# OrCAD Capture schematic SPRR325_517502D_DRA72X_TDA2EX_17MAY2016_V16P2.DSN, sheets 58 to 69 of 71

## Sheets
58 SH69 - POWER MONITOR 2: size B; rev: C
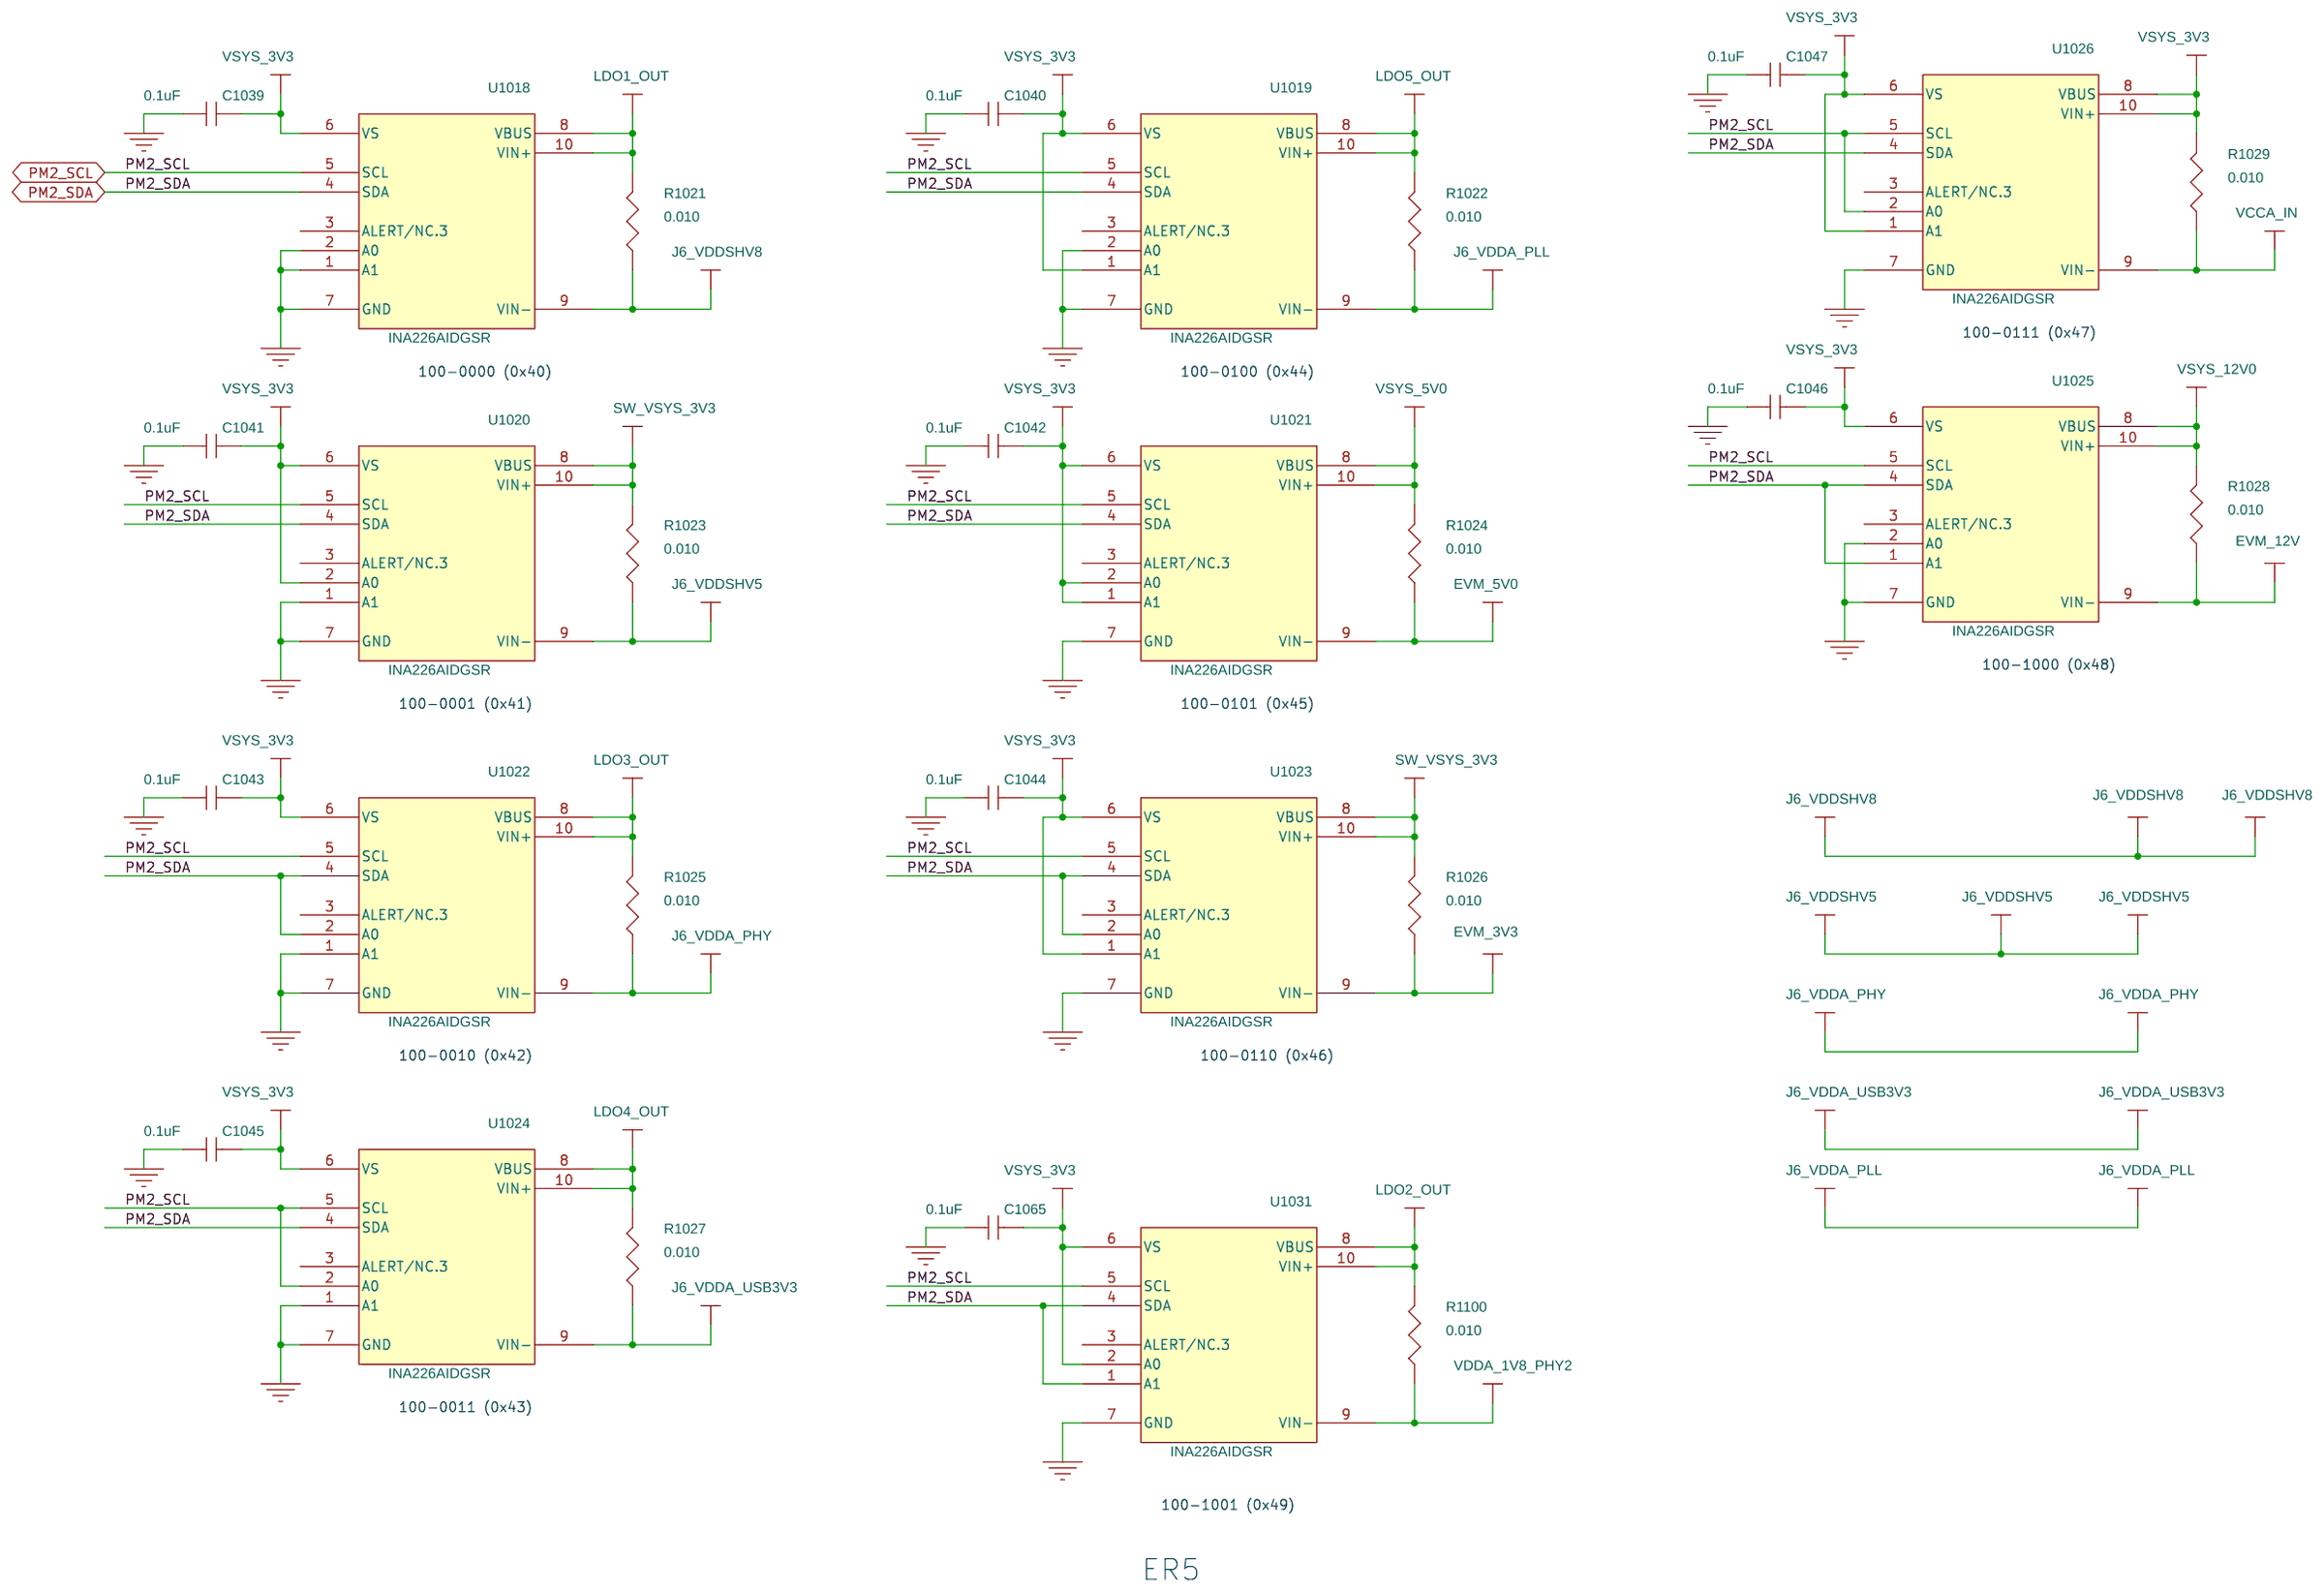
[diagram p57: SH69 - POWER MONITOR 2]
59 SH70 - DARA INTERFACE: size B; rev: C
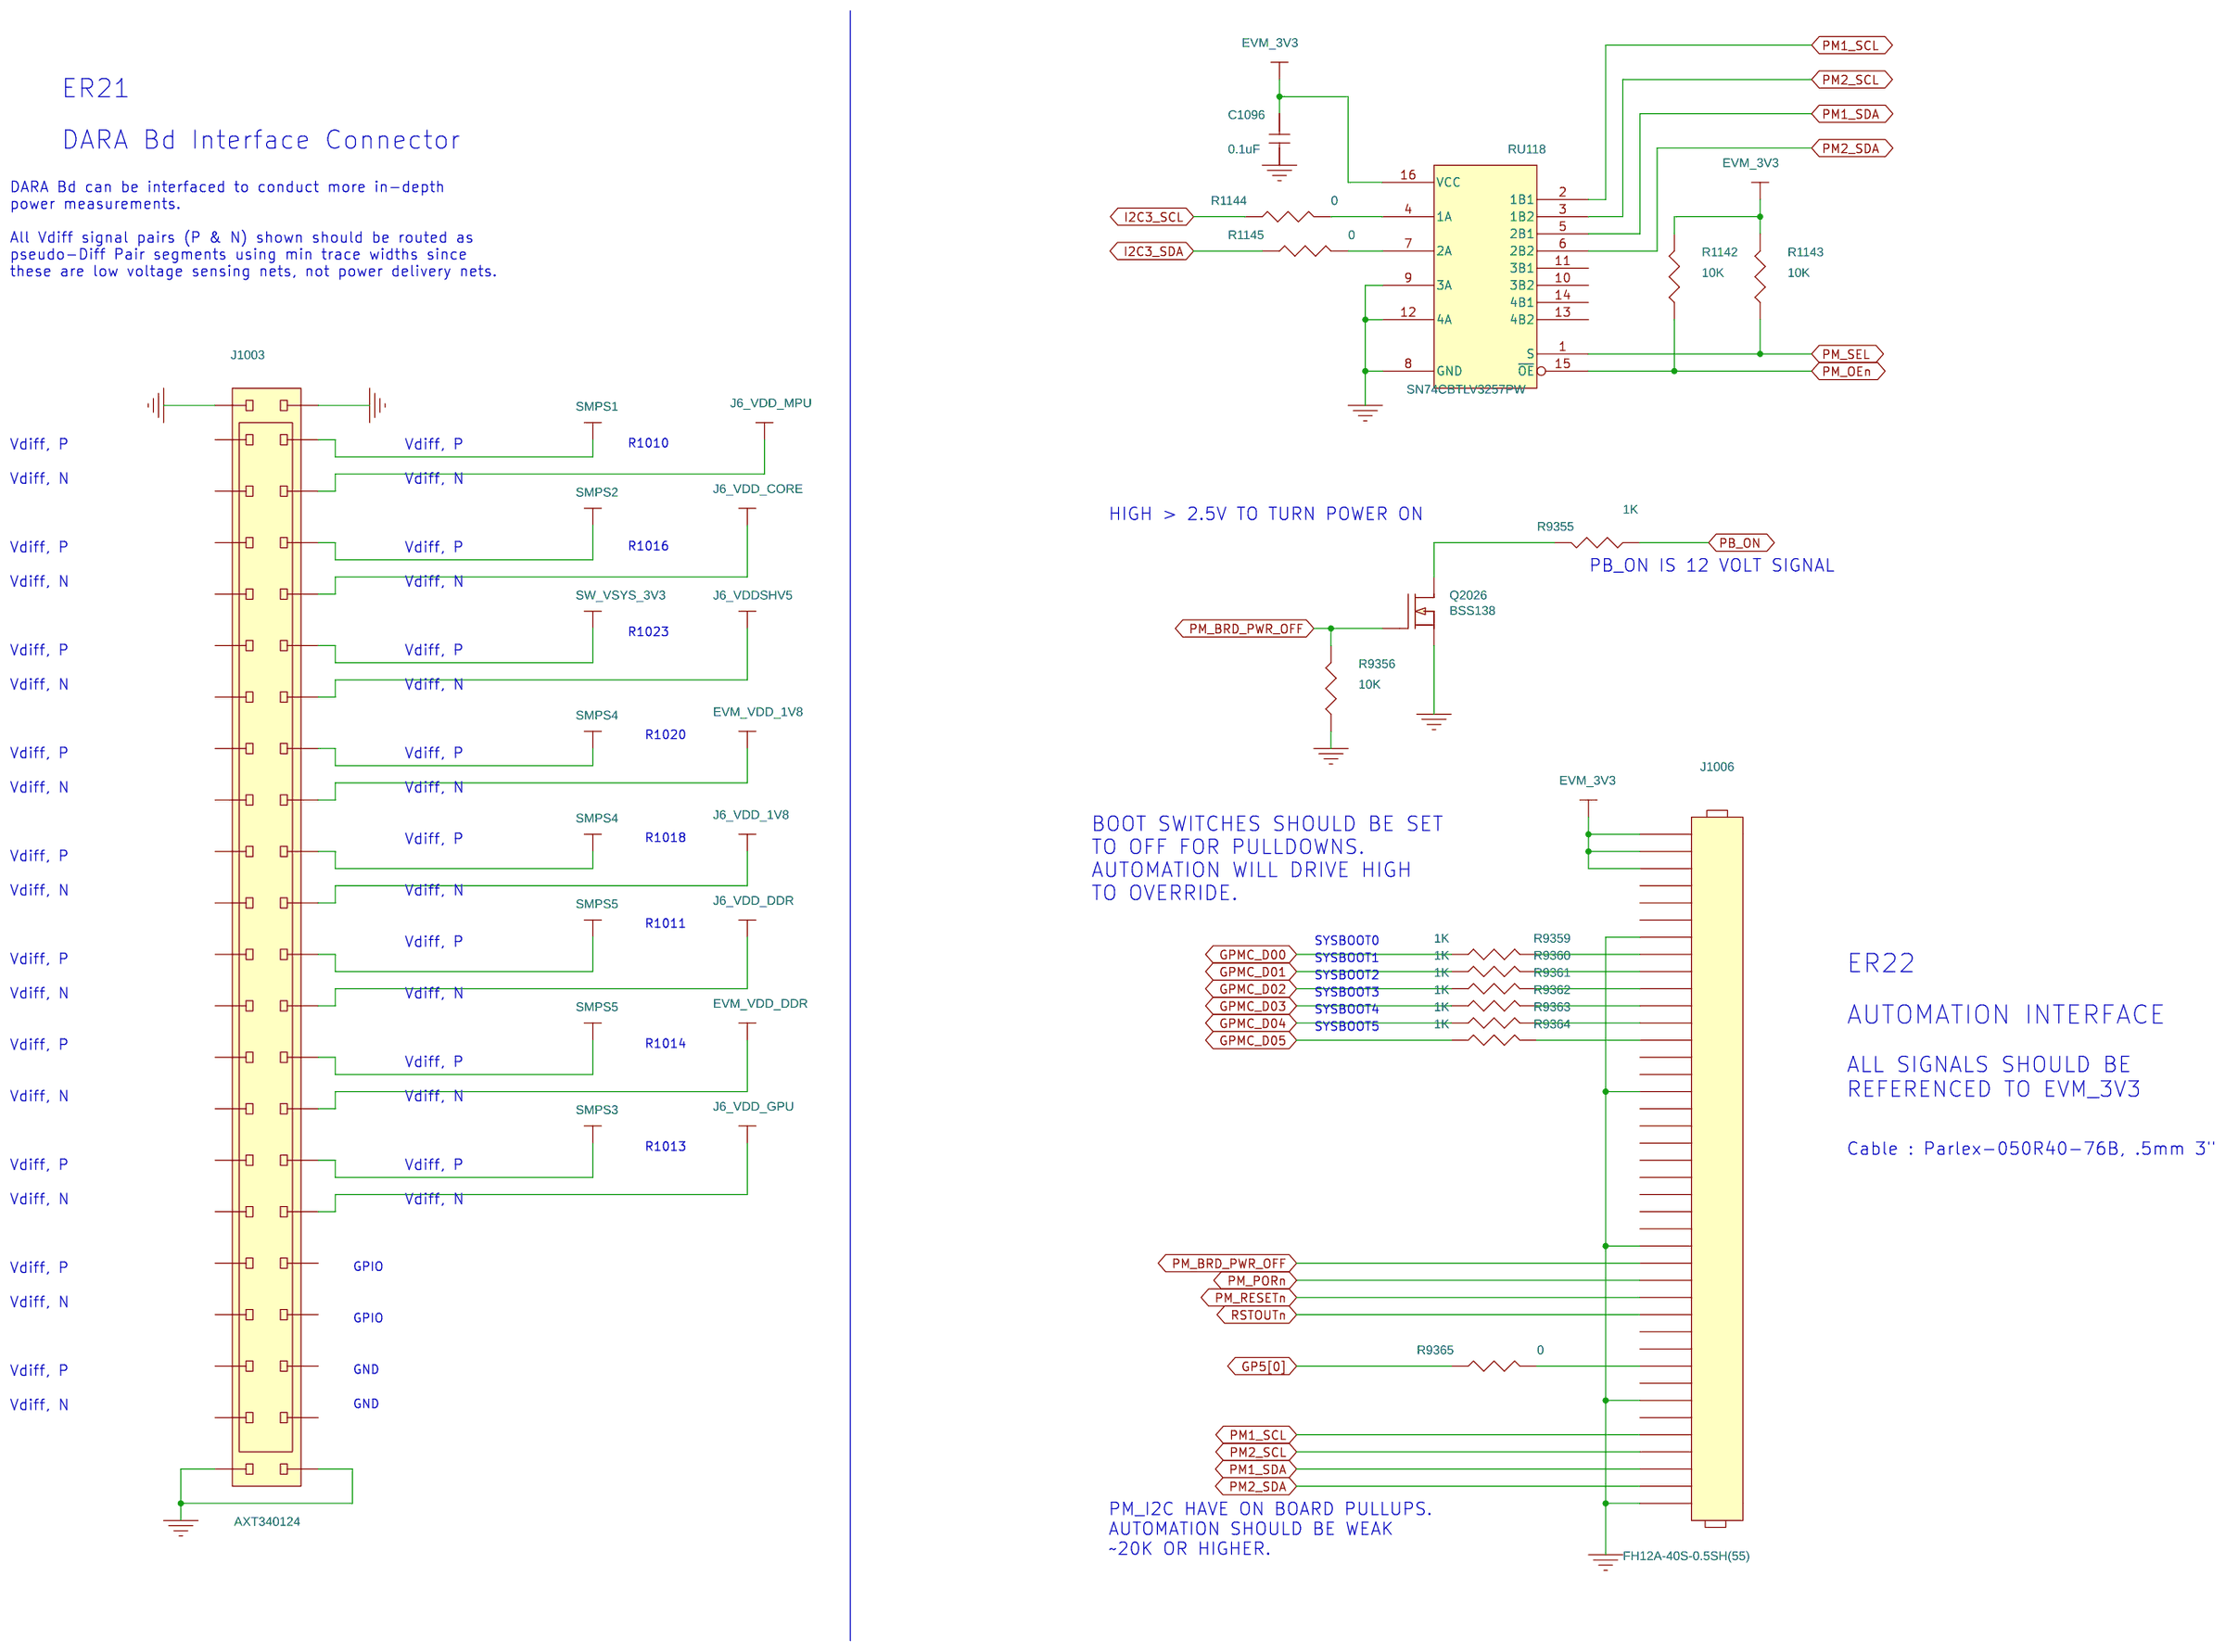
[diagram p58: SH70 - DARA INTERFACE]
60 SH71 - ECN REV B1 TO C
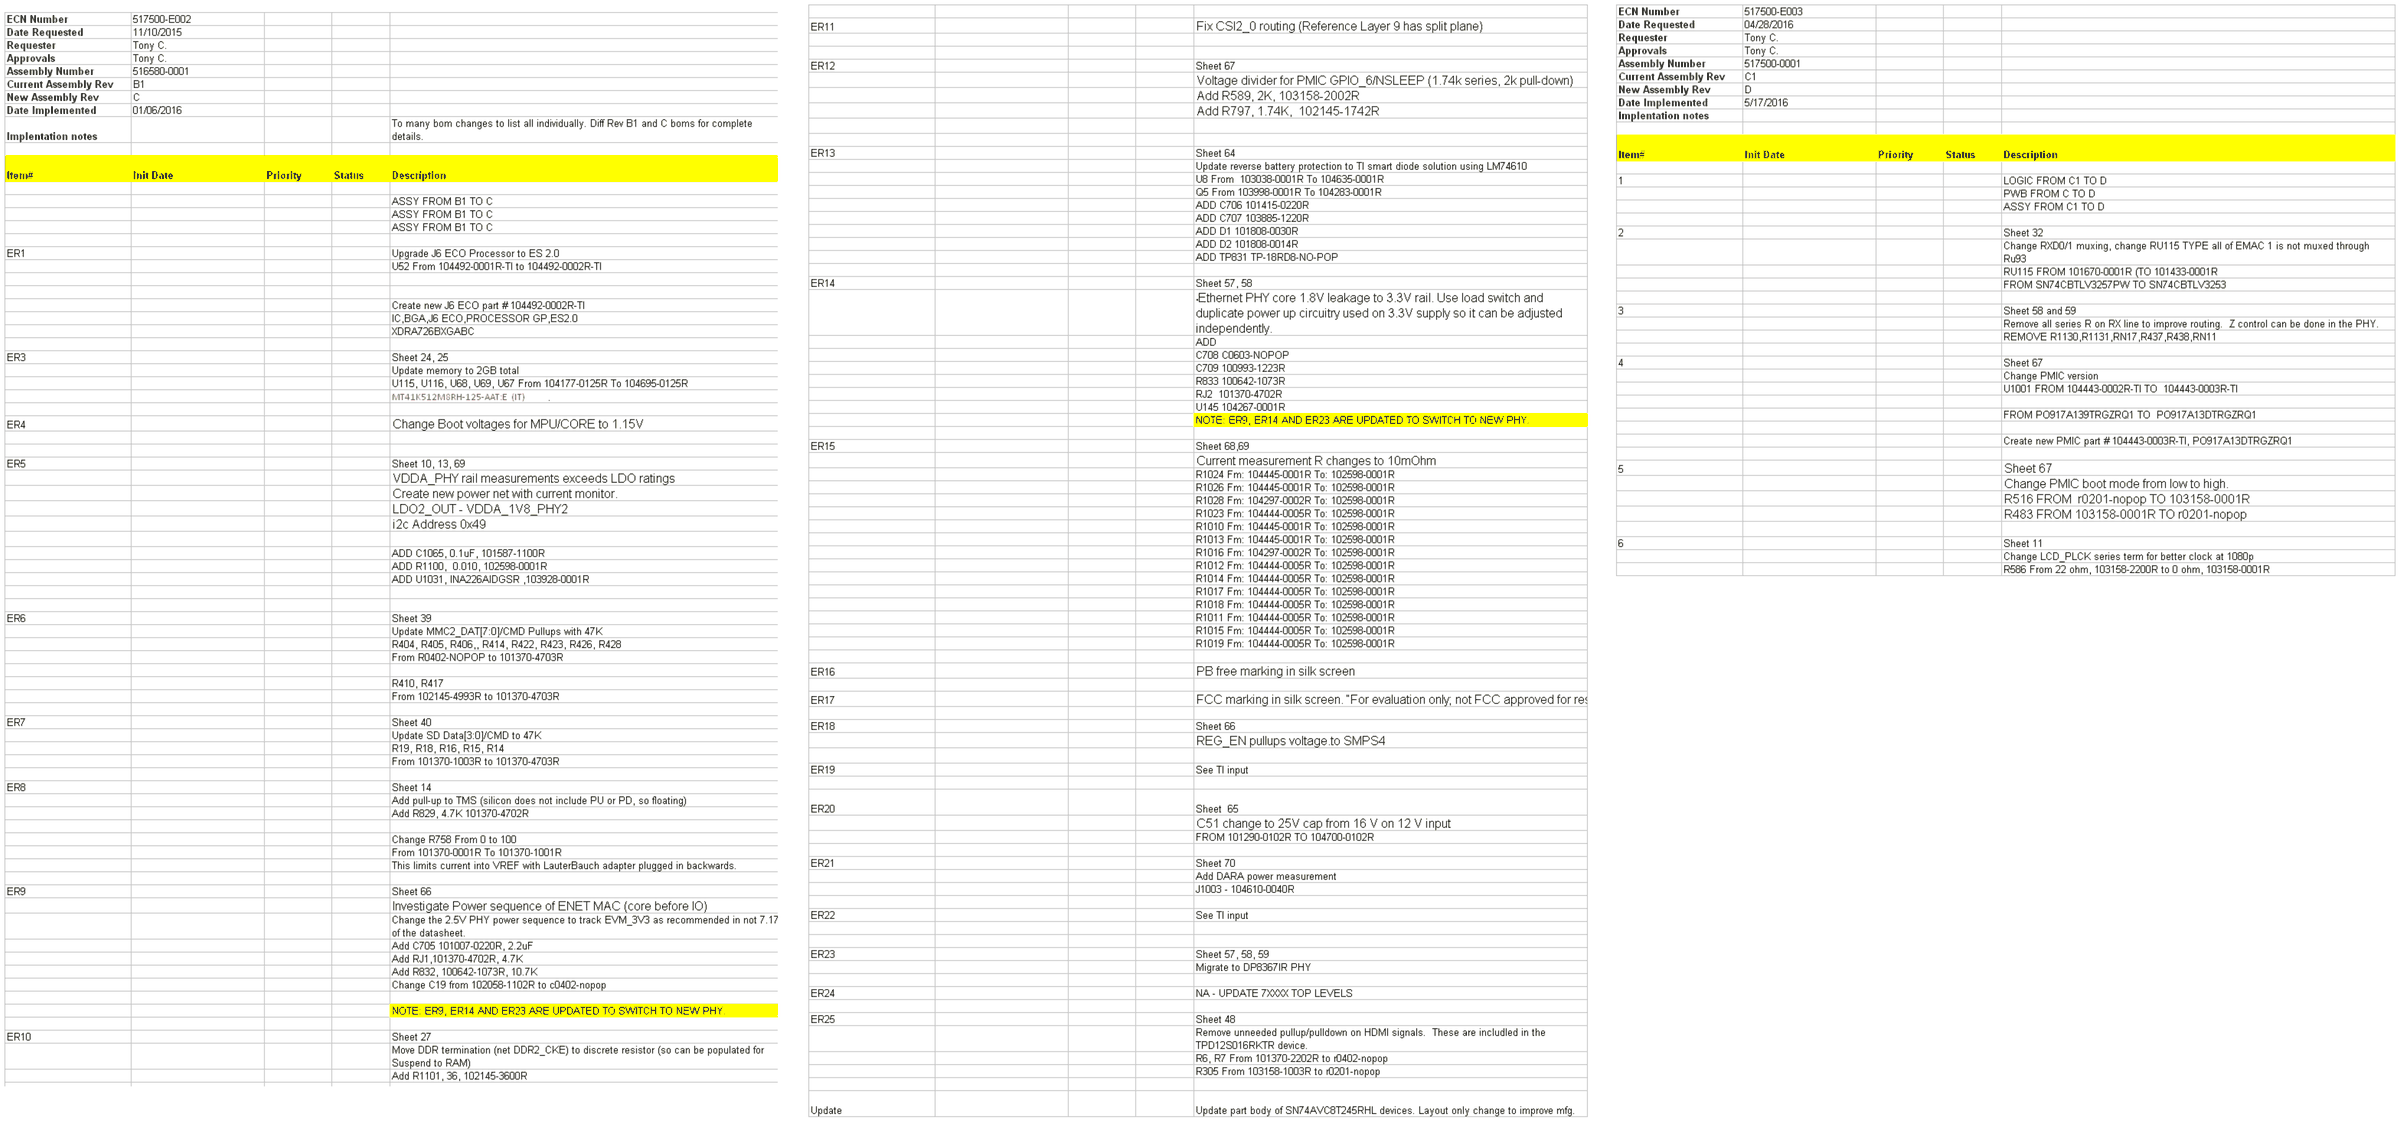
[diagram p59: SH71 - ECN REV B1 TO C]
61 SH04 - SoC SD/MMC IF: size B; rev: A
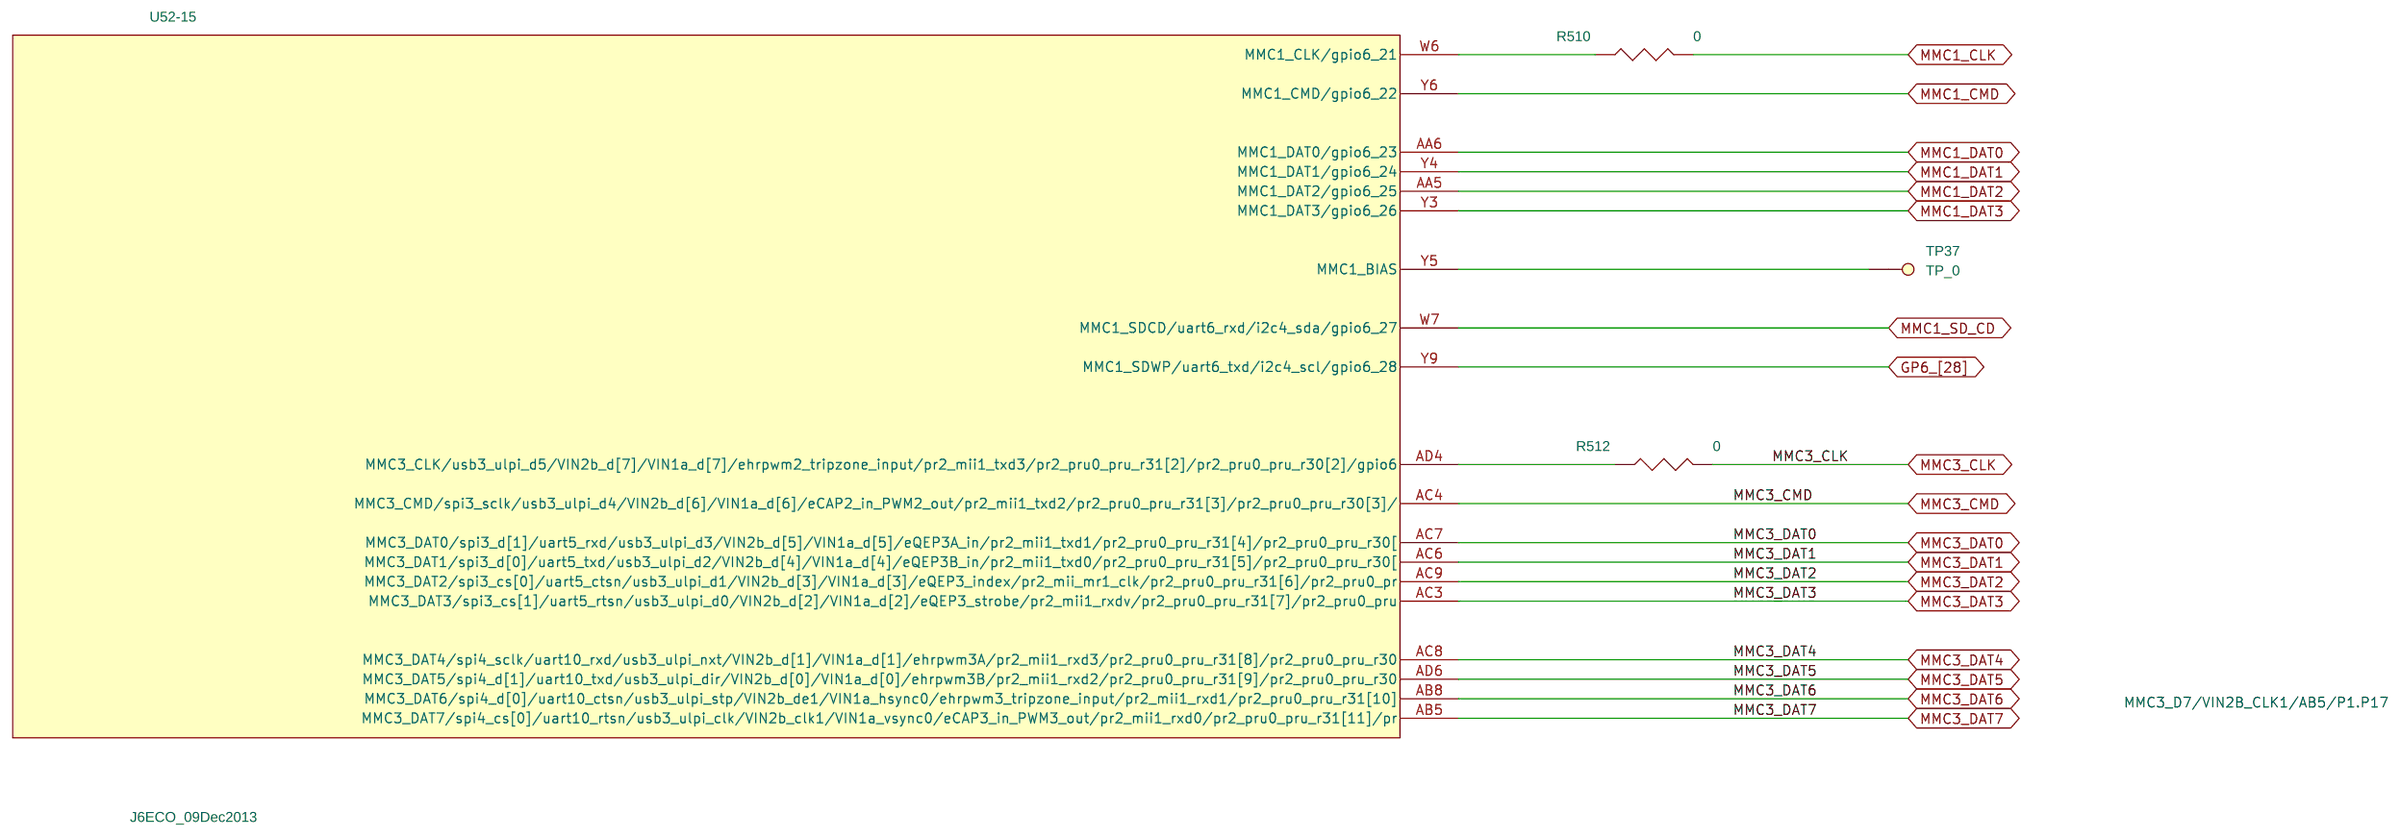
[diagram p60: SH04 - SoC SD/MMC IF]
62 SH03 - SoC SERIAL I/O: size B; rev: C
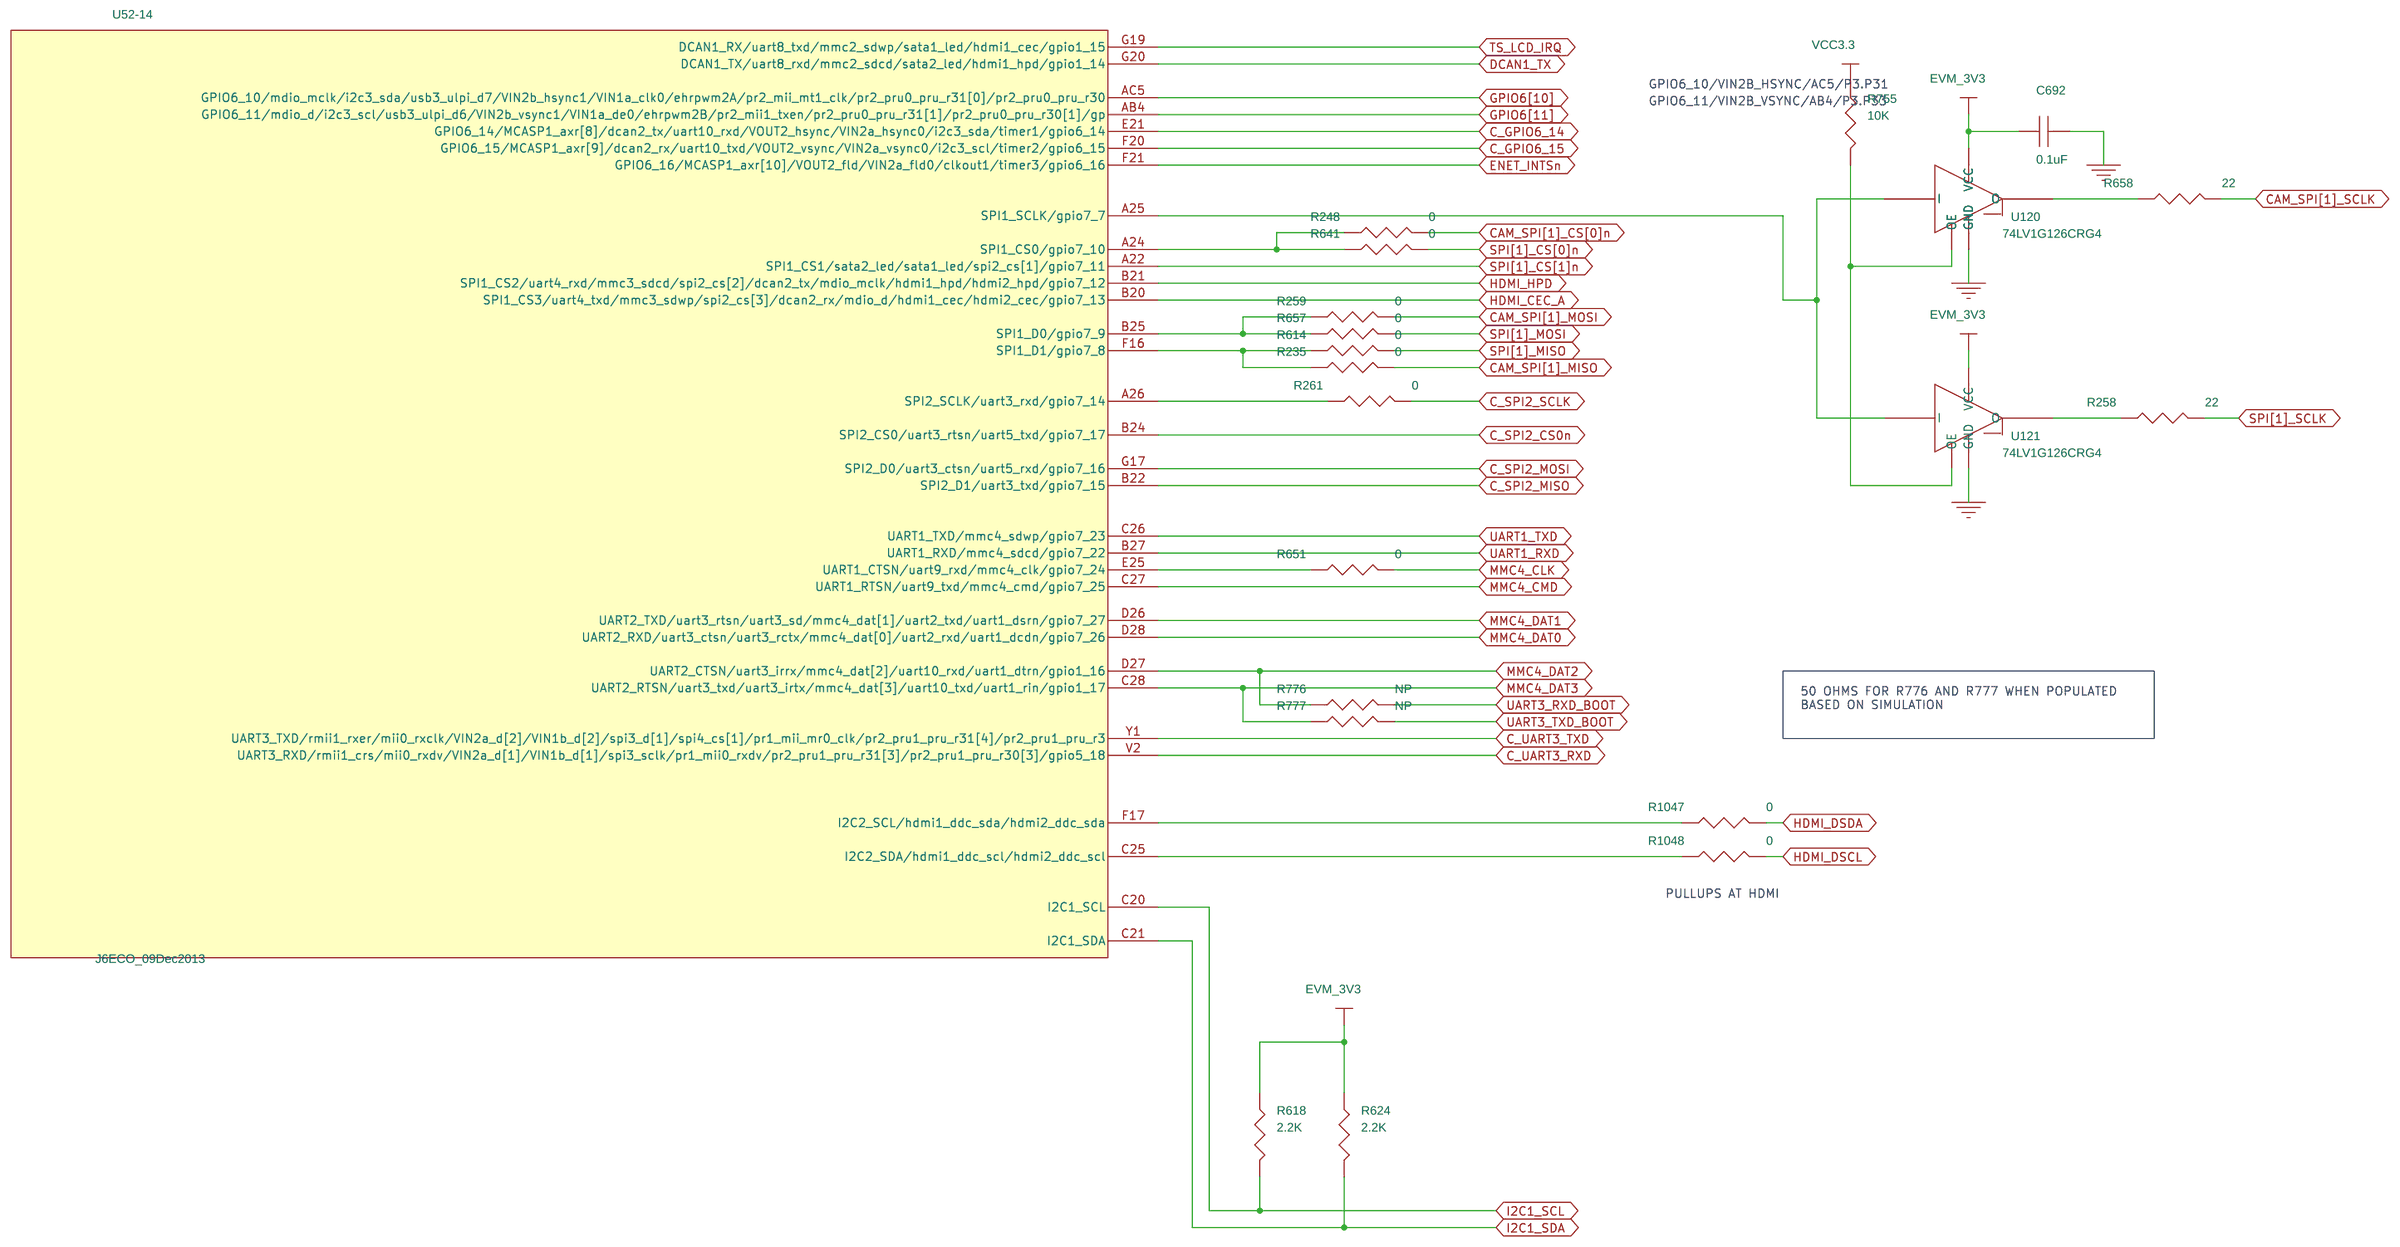
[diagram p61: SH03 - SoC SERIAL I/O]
63 SH29 - MUX B VOUT3/GPMC: size B; rev: C
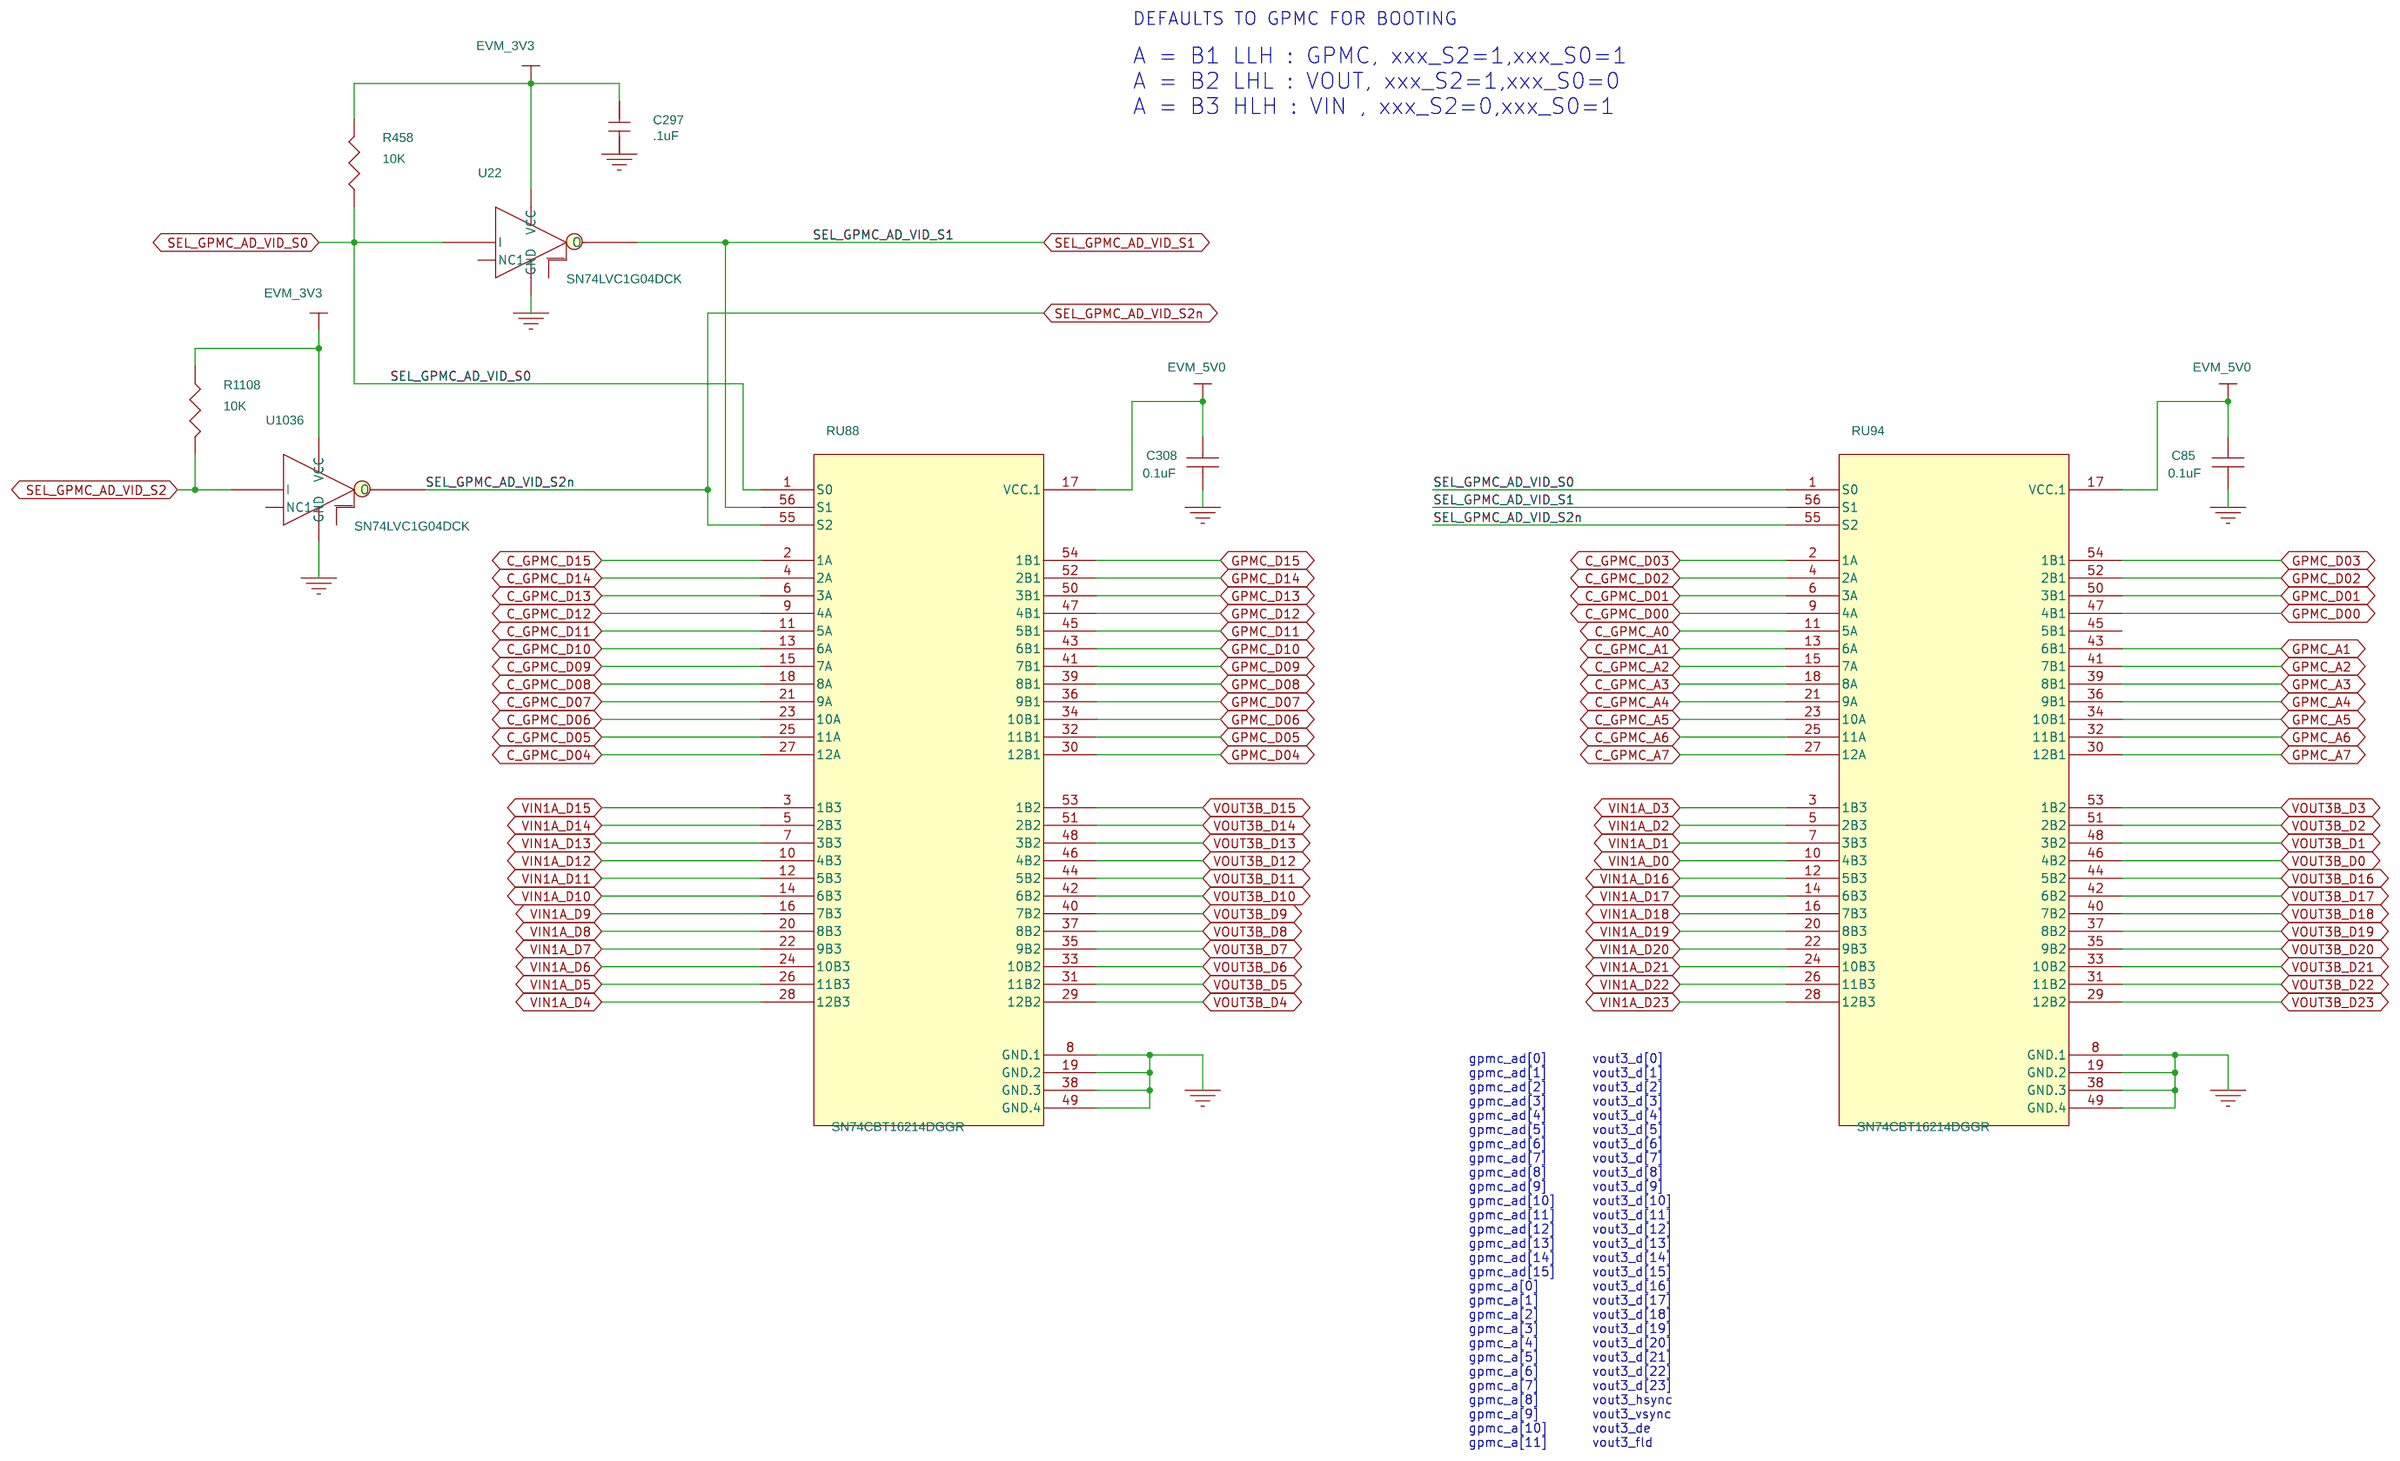
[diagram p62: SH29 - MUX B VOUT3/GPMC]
64 SH06 - SoC ETHERNET/USB: size B; rev: A
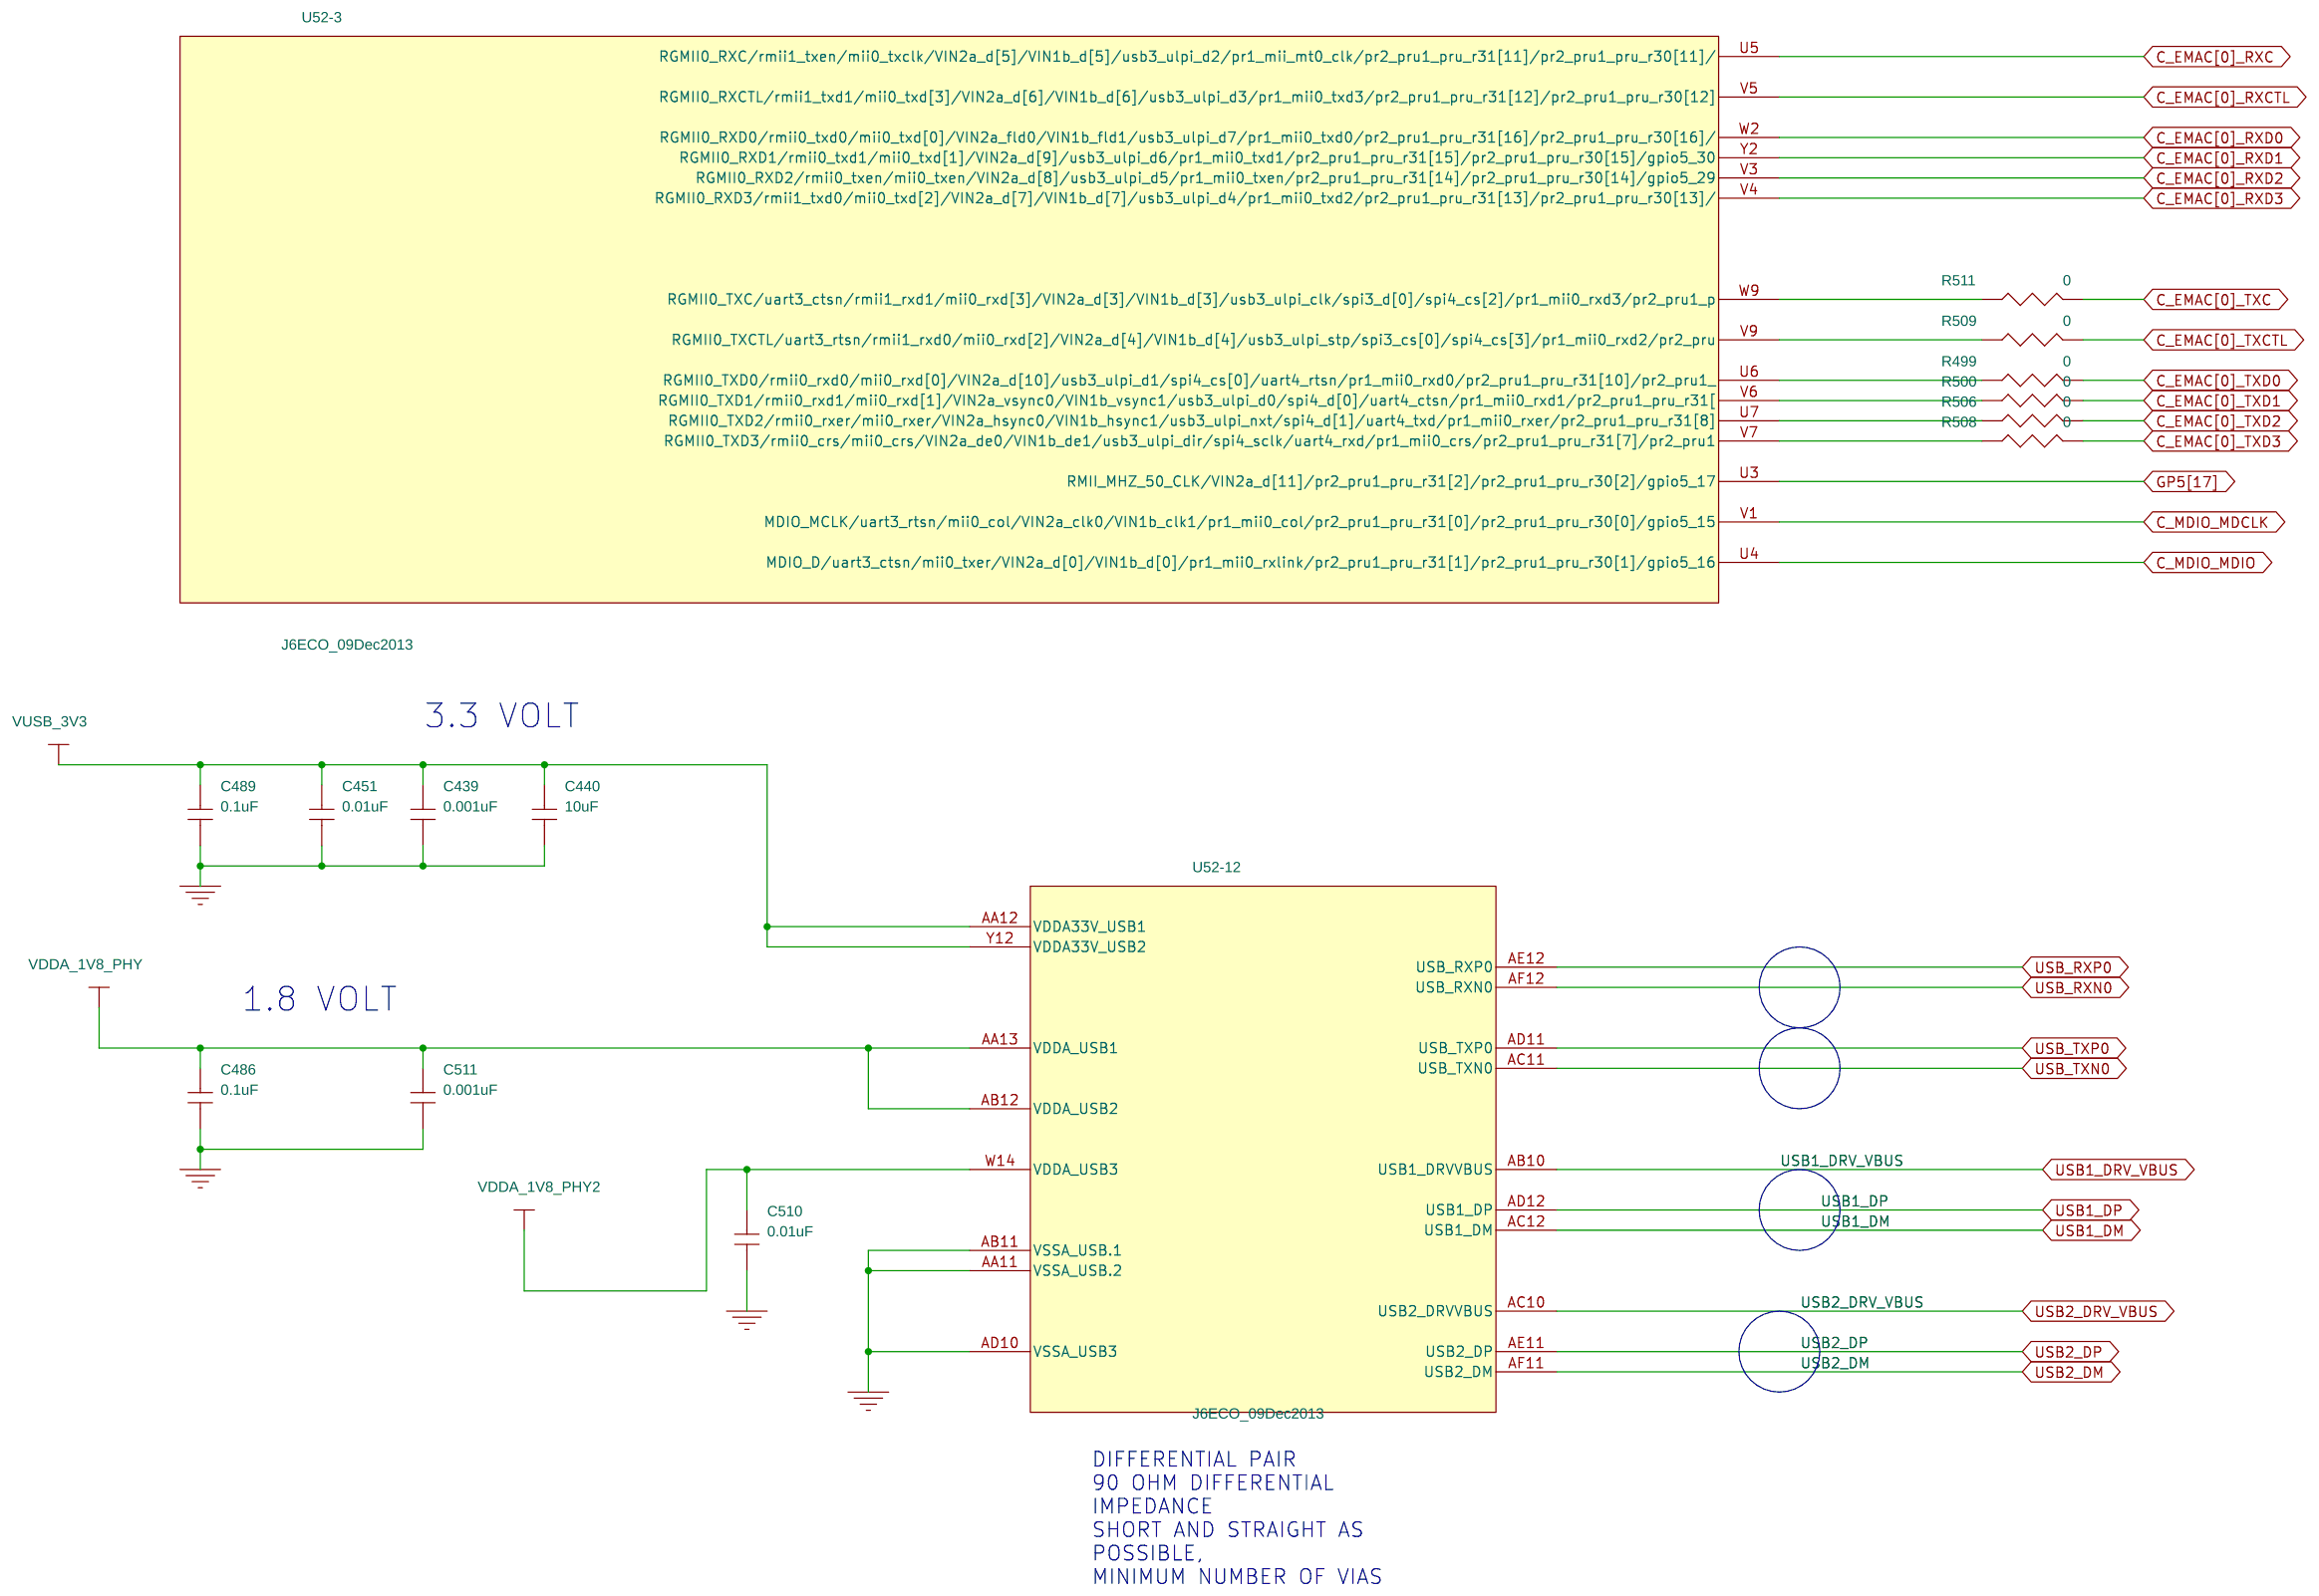
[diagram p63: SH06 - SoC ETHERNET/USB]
65 SH33 - MUX G ENET0/VIN4: size B; rev: C
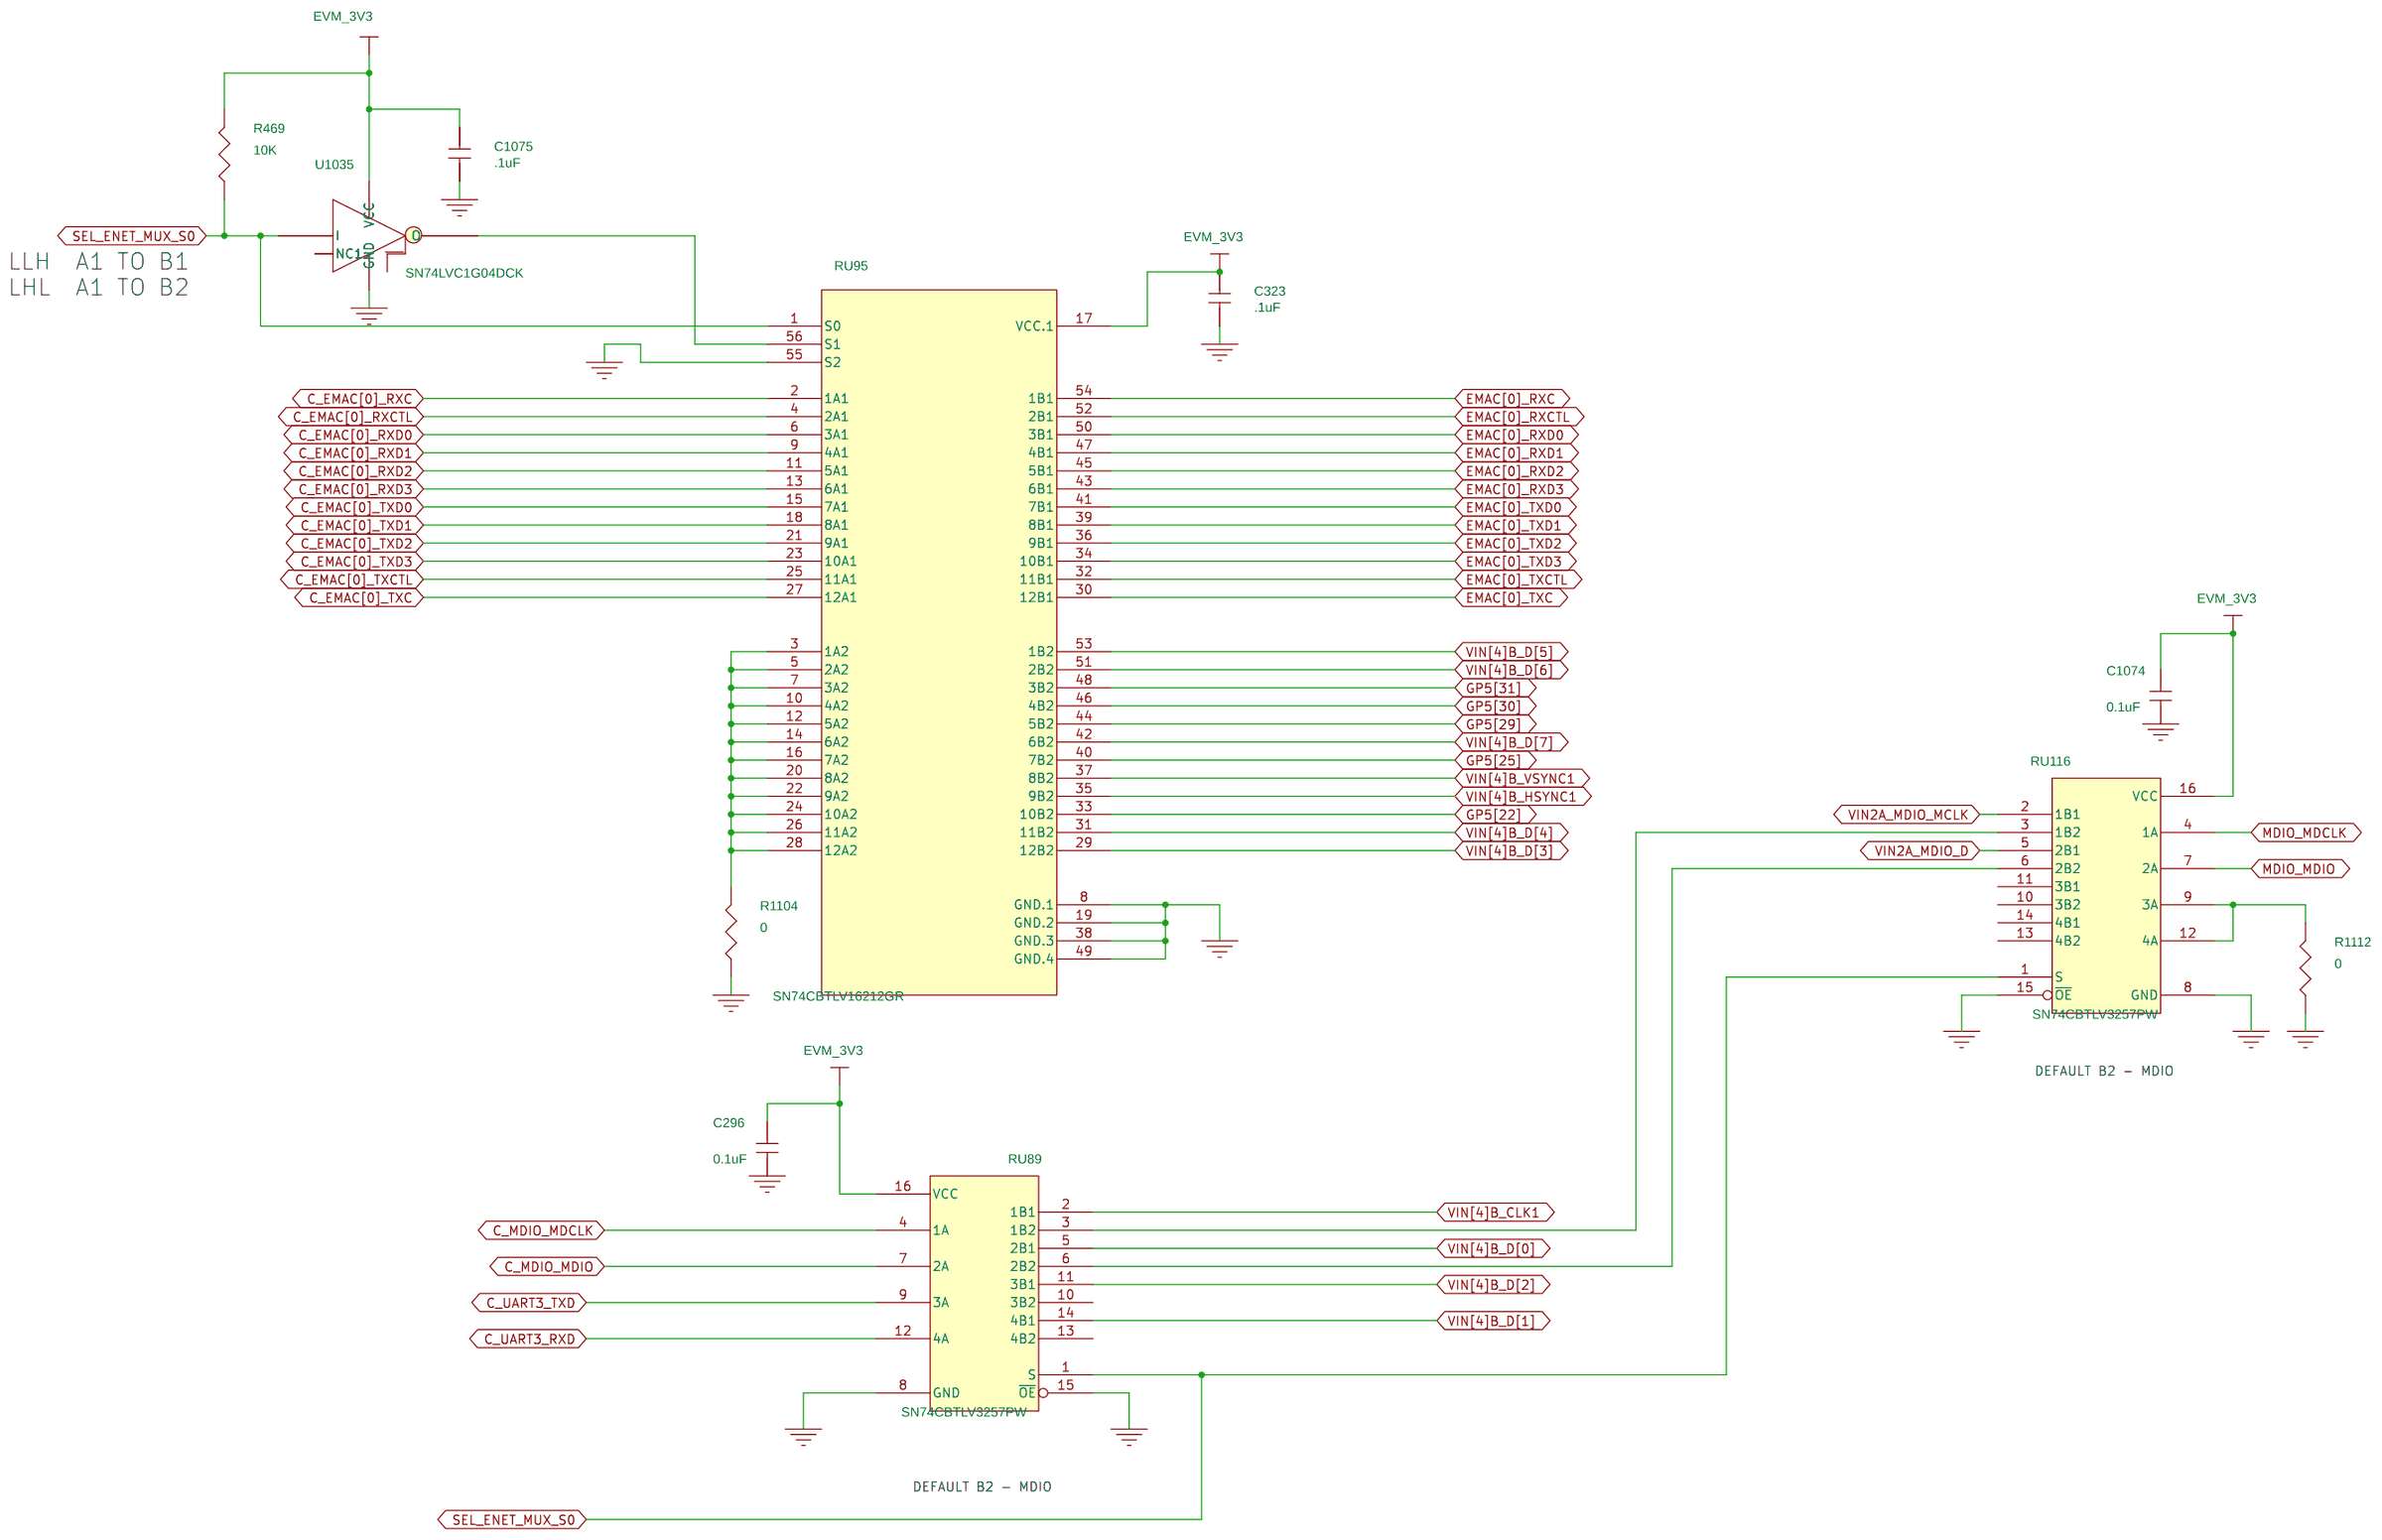
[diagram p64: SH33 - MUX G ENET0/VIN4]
66 SH34 - MUX H MCASP/VIN6A: size B; rev: A
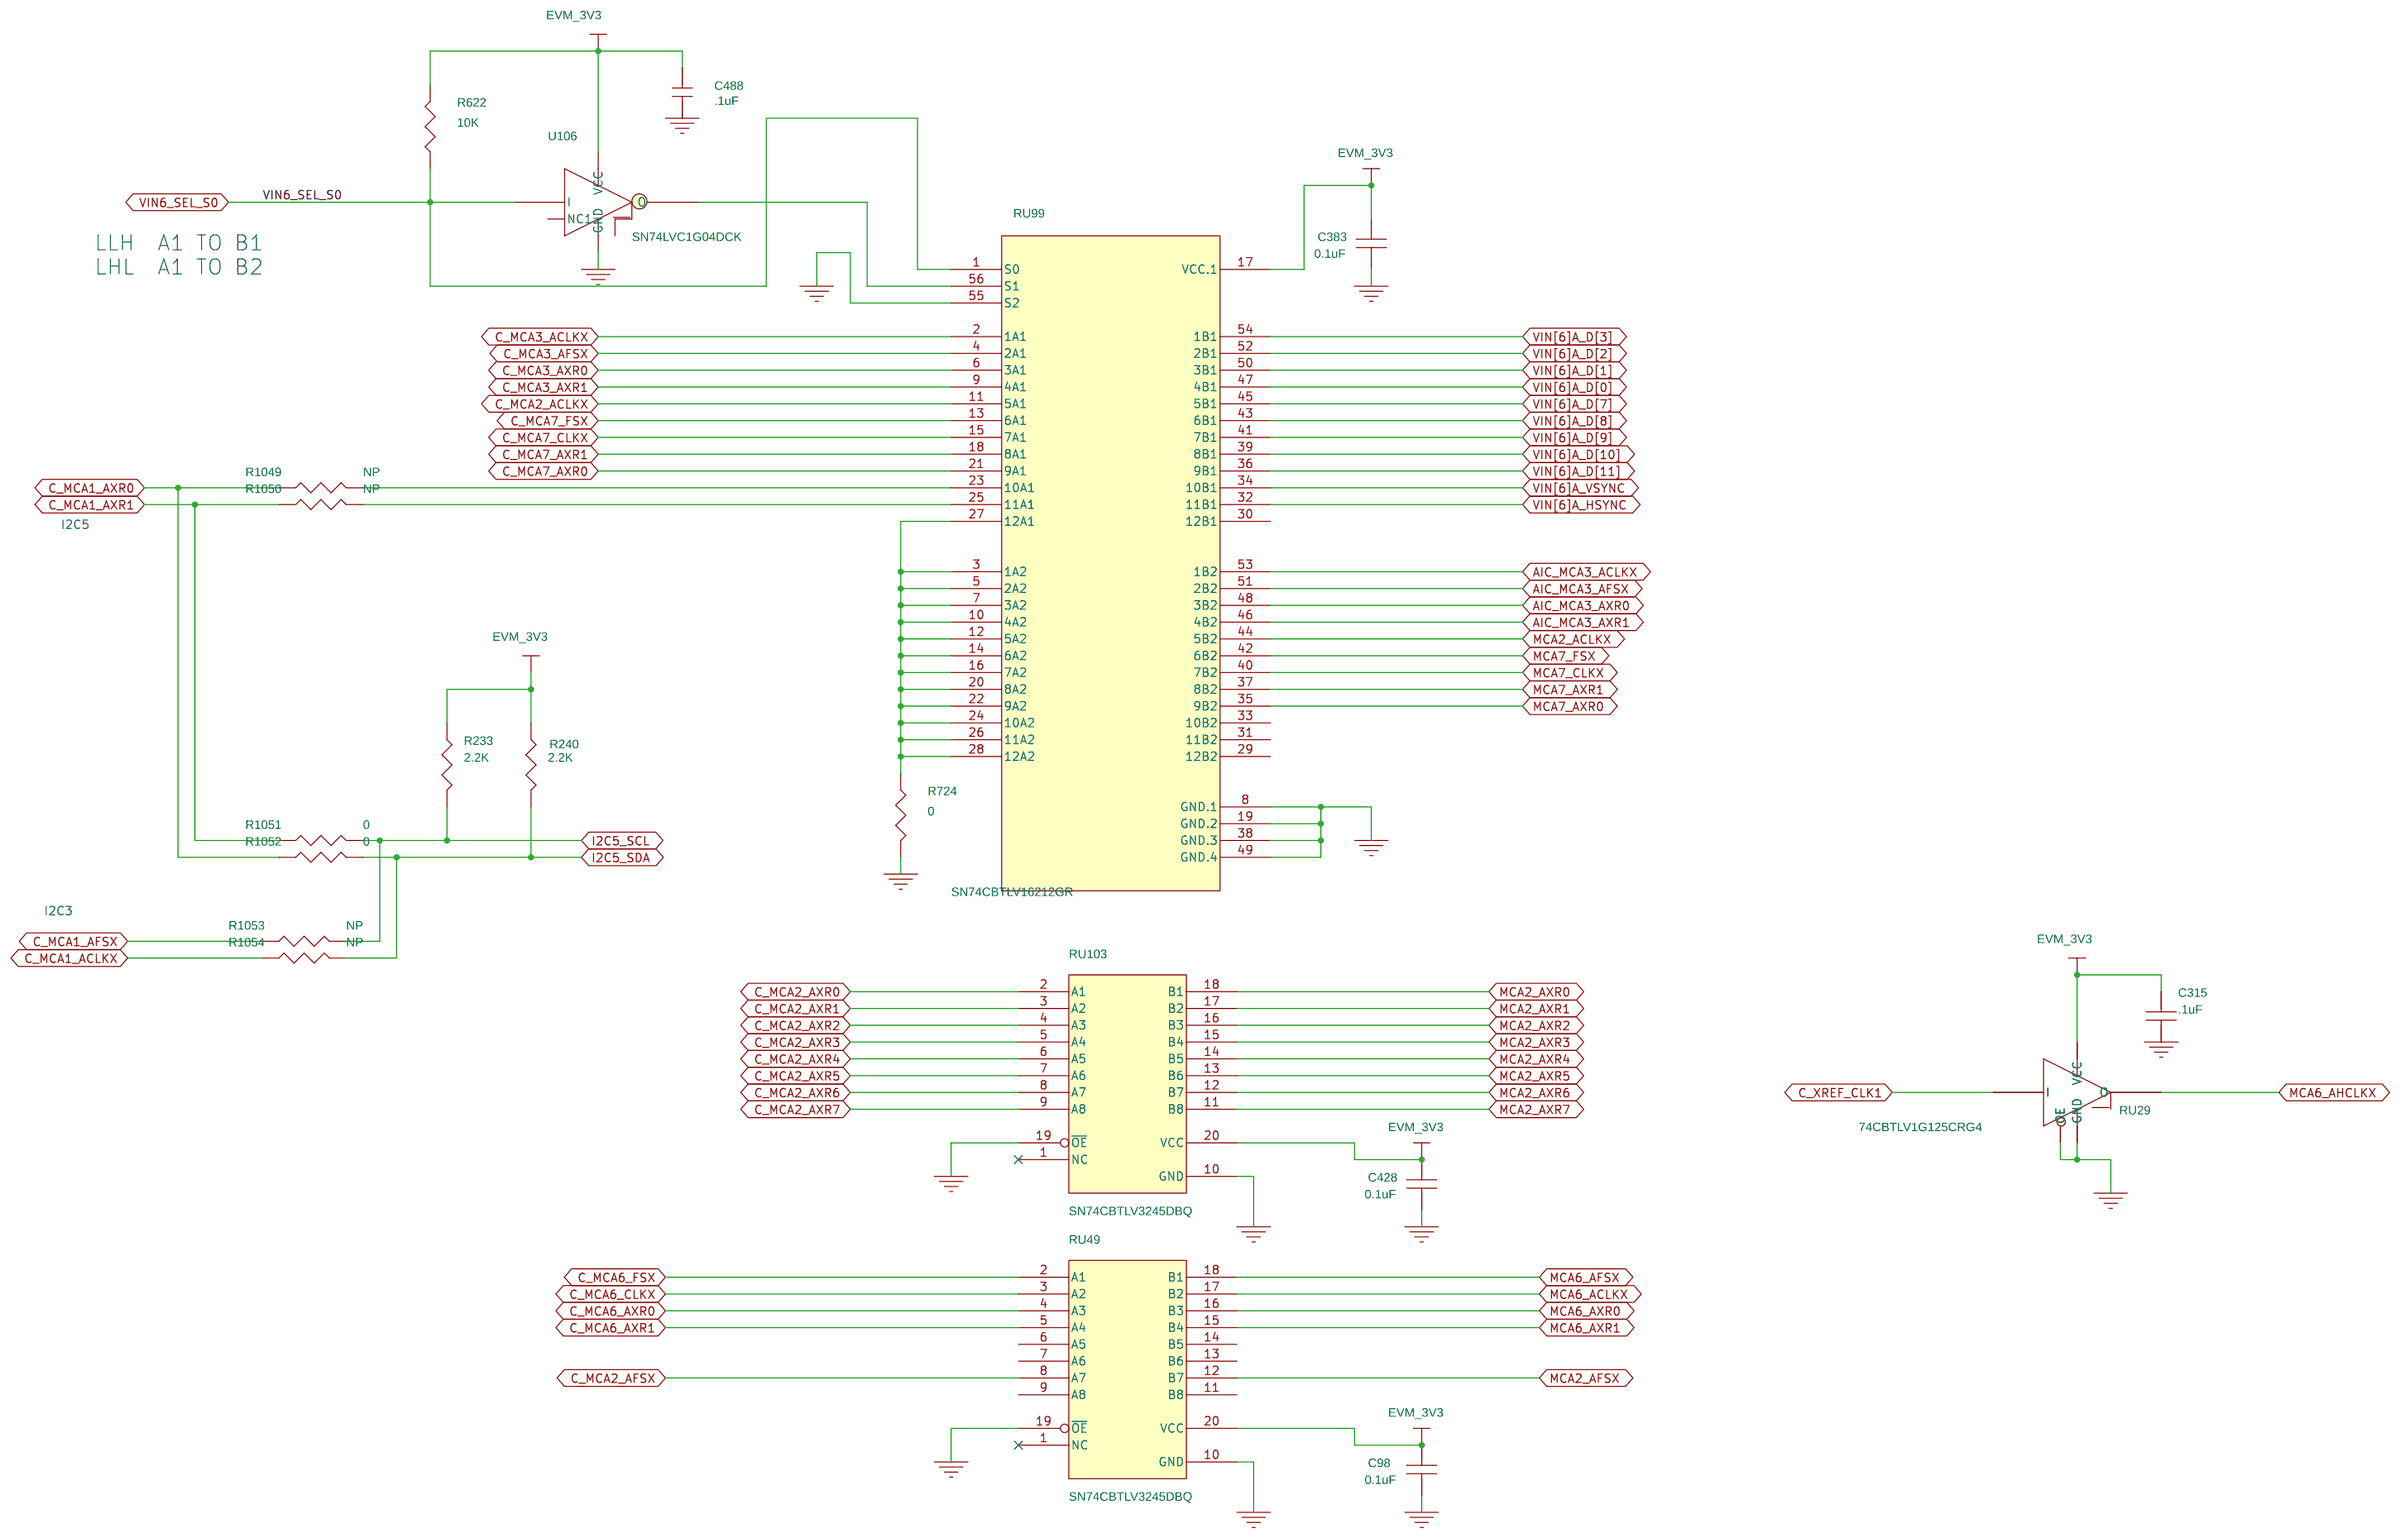
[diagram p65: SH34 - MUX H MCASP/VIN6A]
67 SH35 - MUX J/K/L SERIAL I/O: size B; rev: A
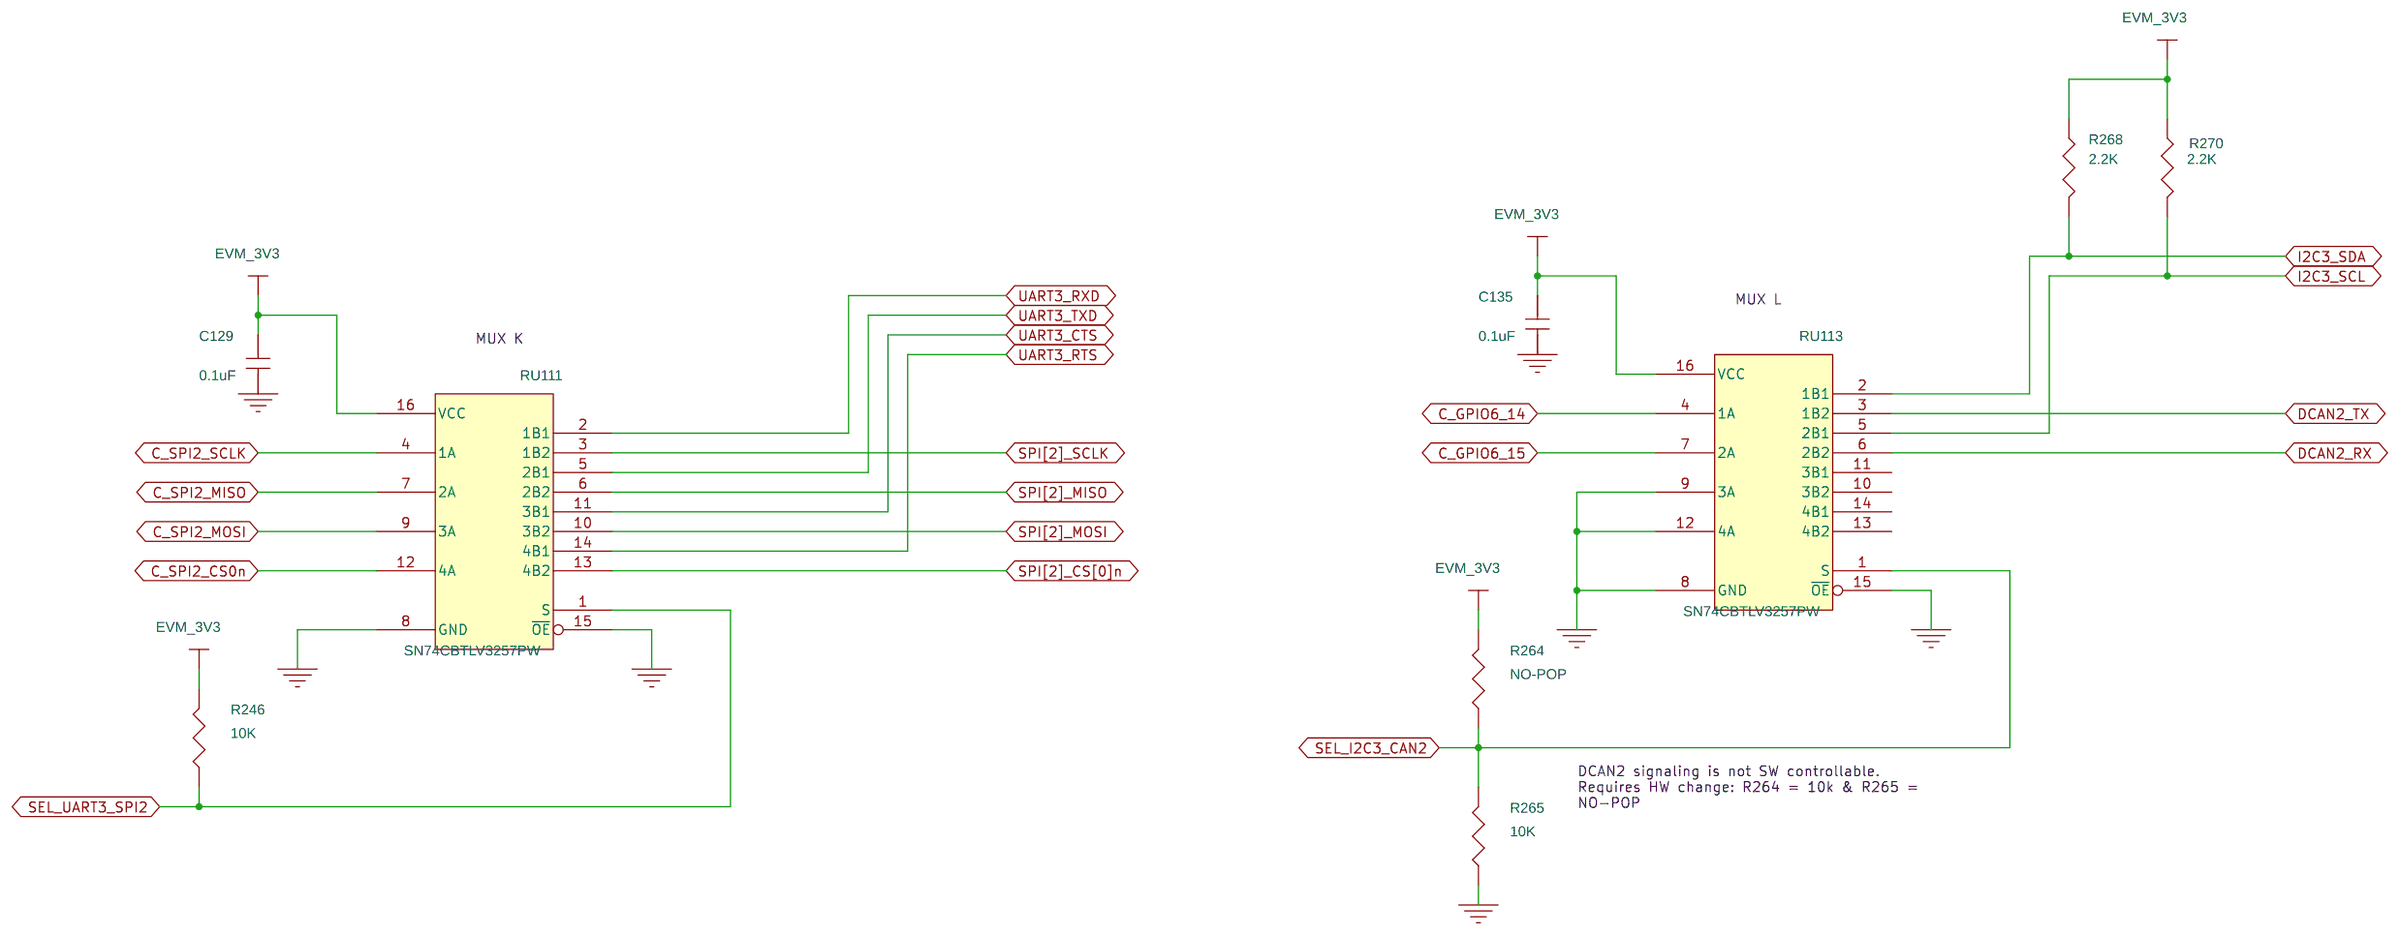
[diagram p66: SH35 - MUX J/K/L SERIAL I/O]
68 SH30 - MUX B VOUT3/GPMC ADD: size B; rev: C
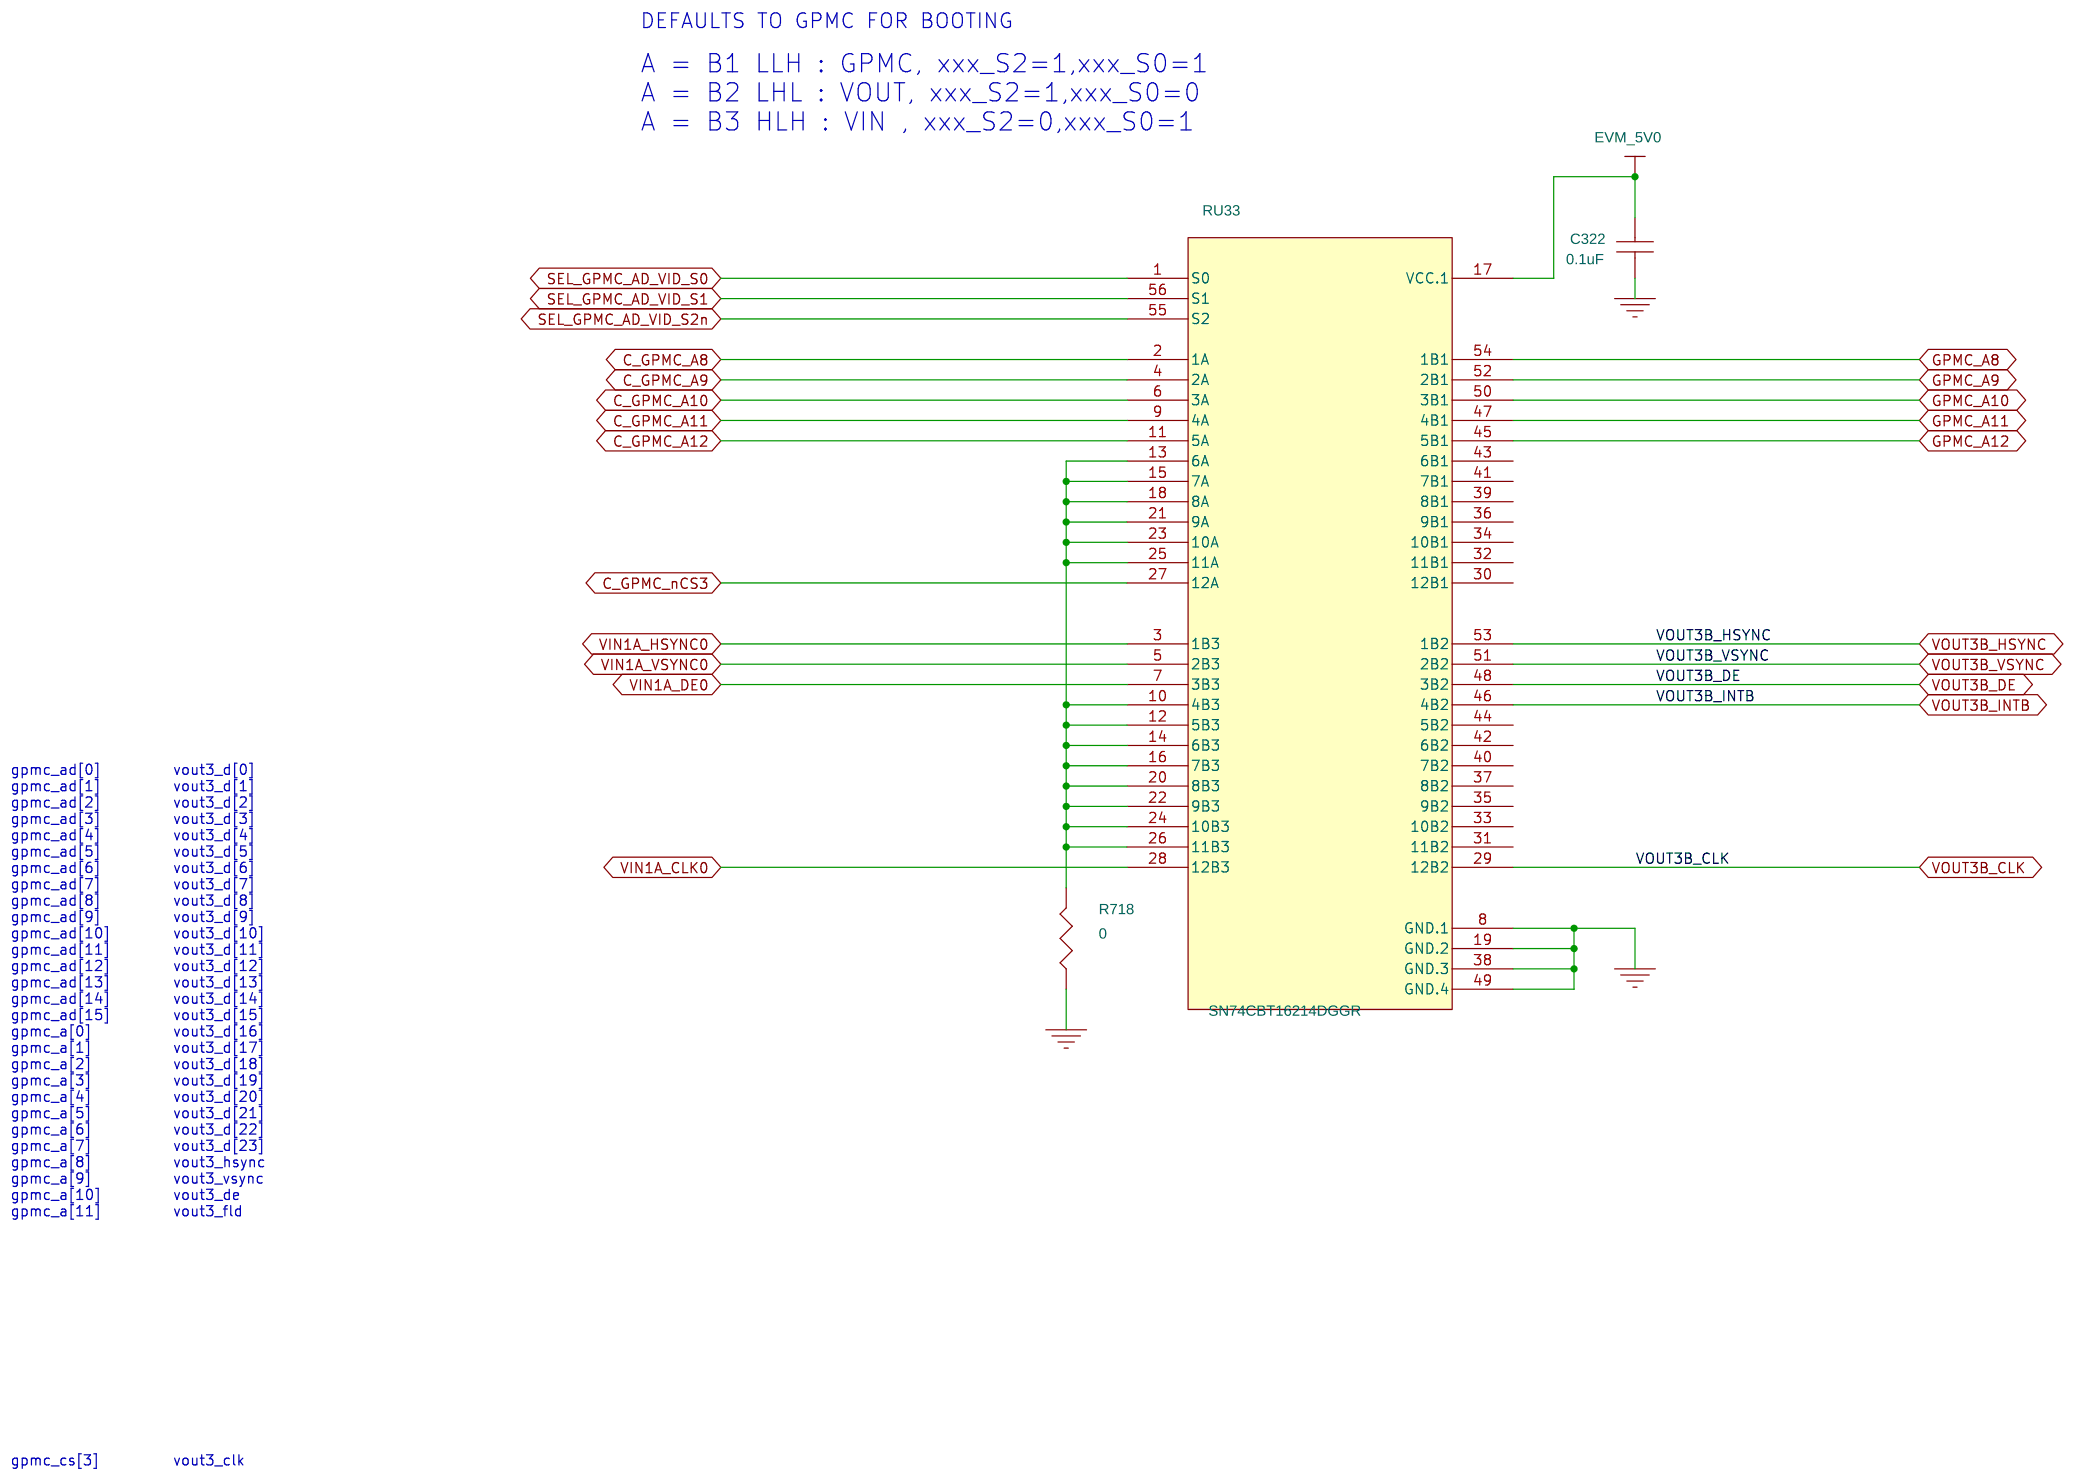
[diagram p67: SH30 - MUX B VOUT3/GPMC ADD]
69 SH52 - I2C EEPROM/TEMP SENSOR: size B; rev: C1
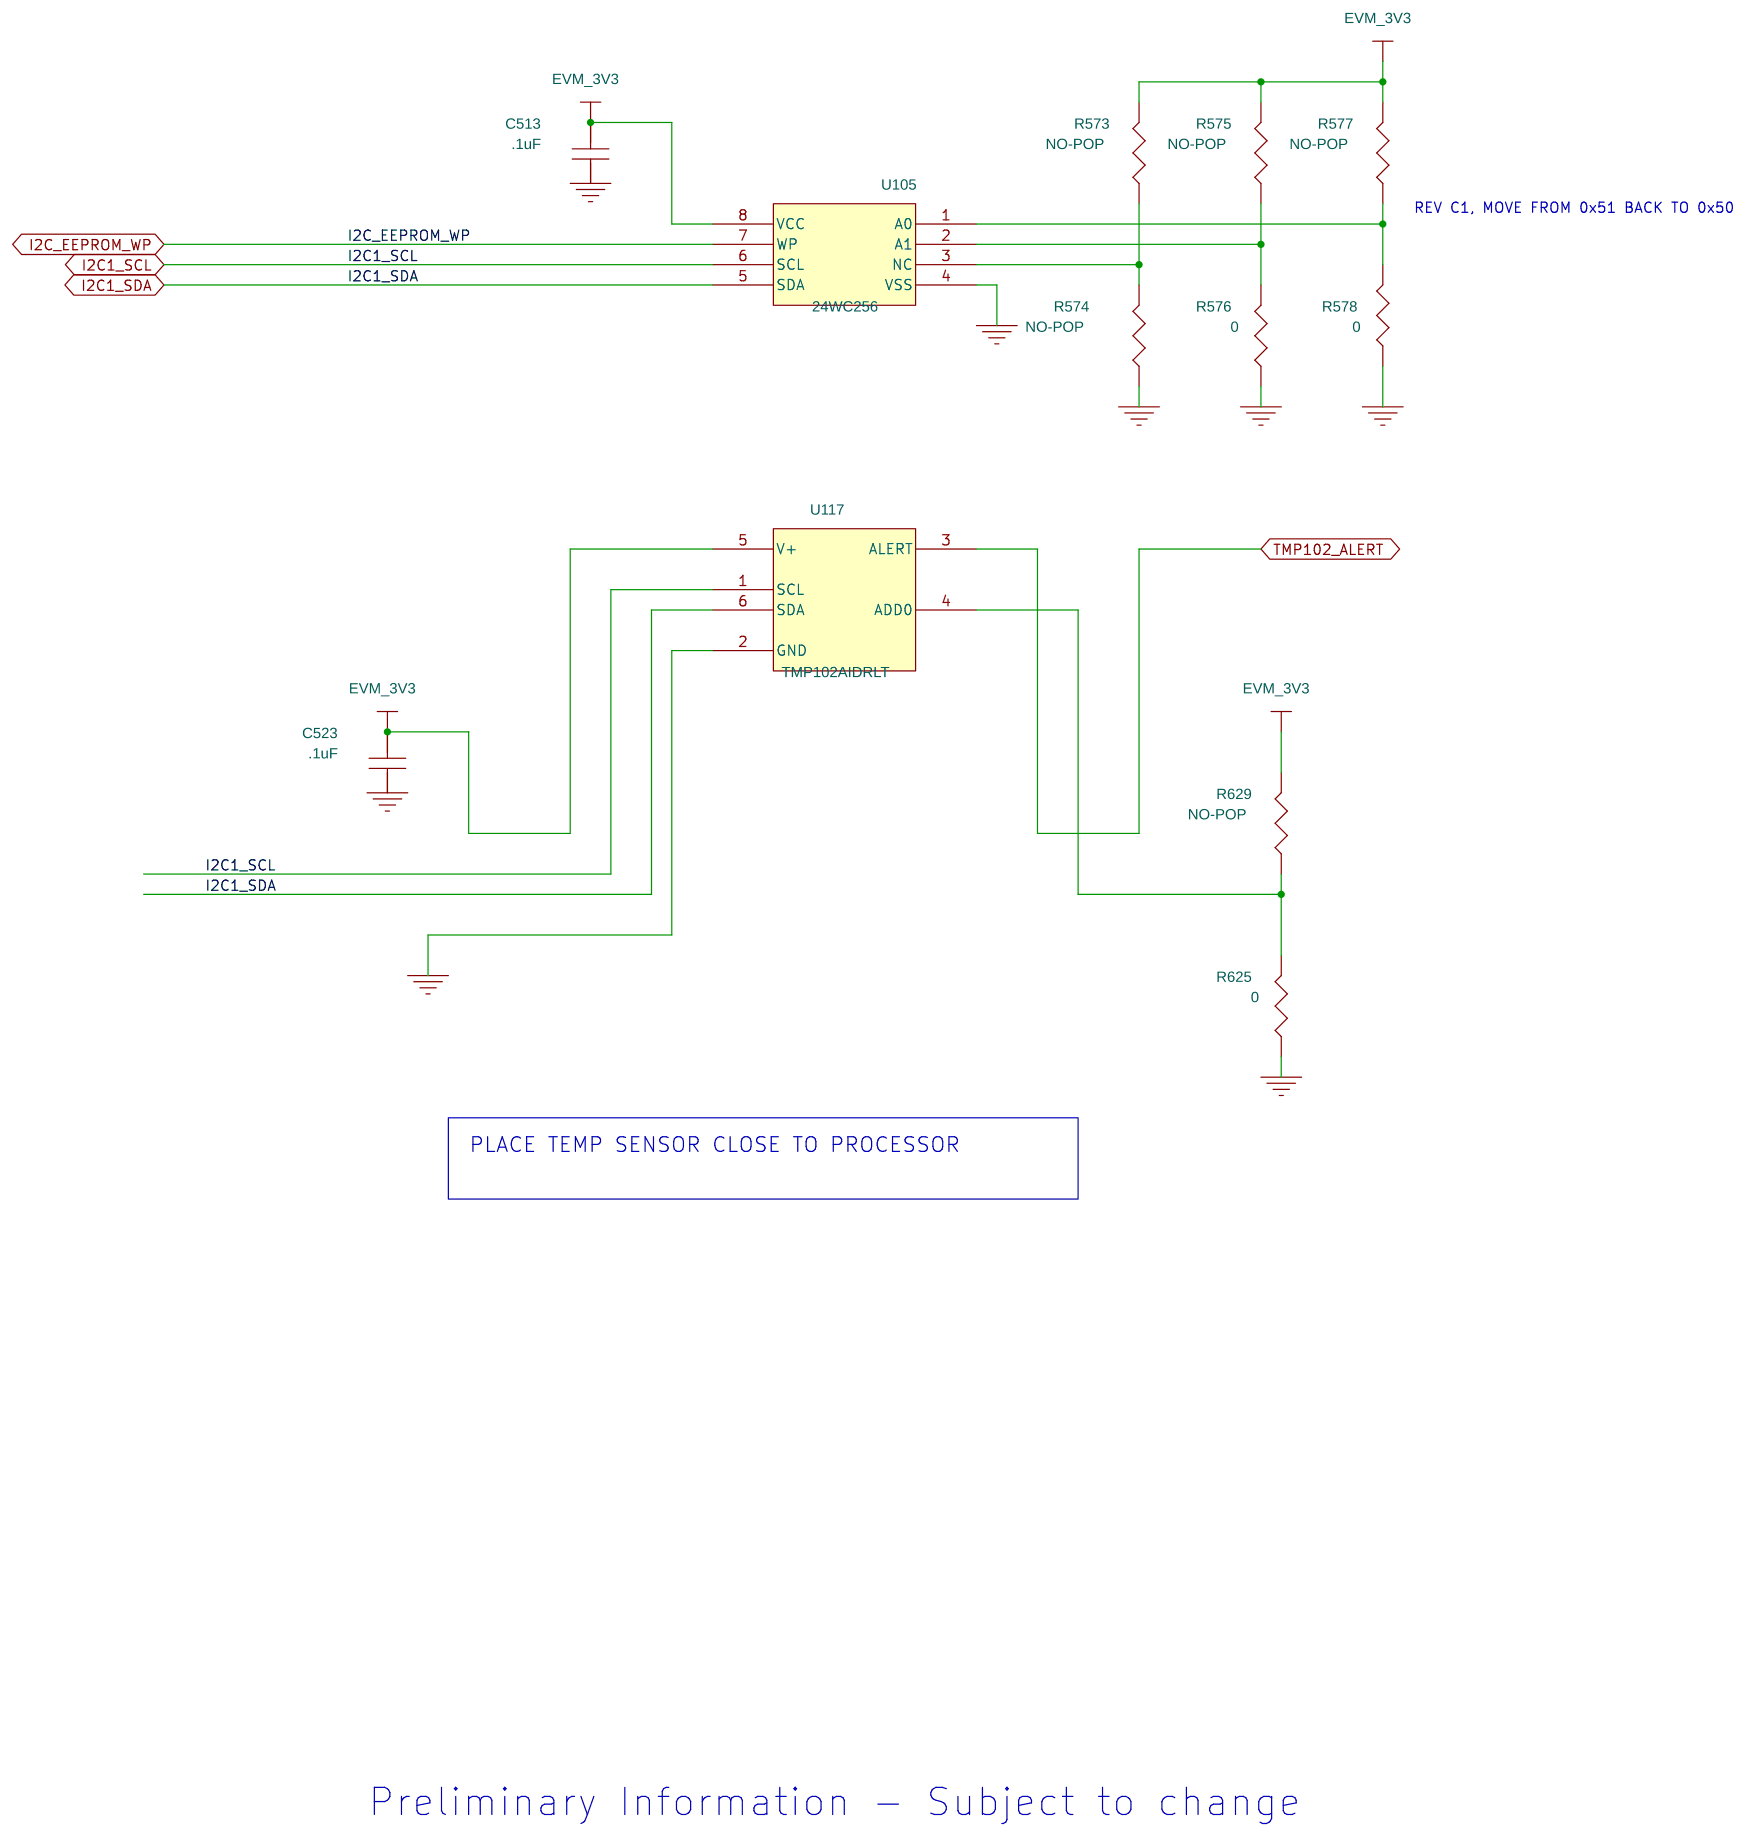
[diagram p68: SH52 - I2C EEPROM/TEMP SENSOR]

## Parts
sheet SH03 - SoC SERIAL I/O
C692  0.1uF  [c402-25]
R235  0  [r201-6p6spc]
R248  0  [r201-6p6spc]
R258  22  [r201-6p6spc]
R259  0  [r201-6p6spc]
R261  0  [r201-6p6spc]
R614  0  [r201-6p6spc]
R618  2.2K  [r402-25]
R624  2.2K  [r402-25]
R641  0  [r201-6p6spc]
R651  0  [r201-6p6spc]
R657  0  [r201-6p6spc]
R658  22  [r201-6p6spc]
R755  10K  [r402-25]
R776  NP  [r201-6p6spc]
R777  NP  [r201-6p6spc]
R1047  0  [r201-6p6spc]
R1048  0  [r201-6p6spc]
U120  74LV1G126CRG4  [dck-5]
U121  74LV1G126CRG4  [dck-5]
sheet SH04 - SoC SD/MMC IF
R510  0  [r201-6p6spc]
R512  0  [r201-6p6spc]
TP37  TP_0  [tp1-18rd8]
sheet SH06 - SoC ETHERNET/USB
C439  0.001uF  [c201-6p6spc]
C440  10uF  [c603-35x45]
C451  0.01uF  [c201-6p6spc]
C486  0.1uF  [c201-6p6spc]
C489  0.1uF  [c201-6p6spc]
C510  0.01uF  [c201-6p6spc]
C511  0.001uF  [c201-6p6spc]
R499  0  [r201-6p6spc]
R500  0  [r201-6p6spc]
R506  0  [r201-6p6spc]
R508  0  [r201-6p6spc]
R509  0  [r201-6p6spc]
R511  0  [r201-6p6spc]
sheet SH17 - SoC IO POWER
U52  J6ECO_09Dec2013  [sktbga-zkk-6334-p760]  (sections -1,-10,-11,-12,-13,-14,-15,-16,-17,-18,-19,-2,-20,-21,-22,-23,-3,-4,-5,-6,-7,-8,-9)
sheet SH29 - MUX B VOUT3/GPMC
C85  0.1uF  [c402-25]
C297  .1uF  [c402-25]
C308  0.1uF  [c402-25]
R458  10K  [r201-6p6spc]
R1108  10K  [r201-6p6spc]
RU88  SN74CBT16214DGGR  [dgg56-12x80]
RU94  SN74CBT16214DGGR  [dgg56-12x80]
U22  SN74LVC1G04DCK  [dck-5]
U1036  SN74LVC1G04DCK  [dck-5]
sheet SH30 - MUX B VOUT3/GPMC ADD
C322  0.1uF  [c402-25]
R718  0  [r201-6p6spc]
RU33  SN74CBT16214DGGR  [dgg56-12x80]
sheet SH33 - MUX G ENET0/VIN4
C296  0.1uF  [c402-25]
C323  .1uF  [c402-25]
C1074  0.1uF  [c402-25]
C1075  .1uF  [c402-25]
R469  10K  [r201-6p6spc]
R1104  0  [r201-6p6spc]
R1112  0  [r201-6p6spc]
RU89  SN74CBTLV3257PW  [tssop16-14x70]
RU95  SN74CBTLV16212GR  [dgg56-12x80]
RU116  SN74CBTLV3257PW  [tssop16-14x70]
U1035  SN74LVC1G04DCK  [dck-5]
sheet SH34 - MUX H MCASP/VIN6A
C98  0.1uF  [c402-25]
C315  .1uF  [c402-25]
C383  0.1uF  [c402-25]
C428  0.1uF  [c402-25]
C488  .1uF  [c402-25]
R233  2.2K  [r402-25]
R240  2.2K  [r402-25]
R622  10K  [r201-6p6spc]
R724  0  [r201-6p6spc]
R1049  NP  [r201-6p6spc]
R1050  NP  [r201-6p6spc]
R1051  0  [r201-6p6spc]
R1052  0  [r201-6p6spc]
R1053  NP  [r201-6p6spc]
R1054  NP  [r201-6p6spc]
RU29  74CBTLV1G125CRG4  [dck-5]
RU49  SN74CBTLV3245DBQ  [dbq20-14X70]
RU99  SN74CBTLV16212GR  [dgg56-12x80]
RU103  SN74CBTLV3245DBQ  [dbq20-14X70]
U106  SN74LVC1G04DCK  [dck-5]
sheet SH35 - MUX J/K/L SERIAL I/O
C129  0.1uF  [c402-25]
C135  0.1uF  [c402-25]
R246  10K  [r201-6p6spc]
R264  NO-POP  [r201-6p6spc]
R265  10K  [r201-6p6spc]
R268  2.2K  [r402-25]
R270  2.2K  [r402-25]
RU111  SN74CBTLV3257PW  [tssop16-14x70]
RU113  SN74CBTLV3257PW  [tssop16-14x70]
sheet SH52 - I2C EEPROM/TEMP SENSOR
C513  .1uF  [c402-25]
C523  .1uF  [c402-25]
R573  NO-POP  [r402-25]
R574  NO-POP  [r402-25]
R575  NO-POP  [r402-25]
R576  0  [r402-25]
R577  NO-POP  [r402-25]
R578  0  [r402-25]
R625  0  [r402-25]
R629  NO-POP  [r402-25]
U105  24WC256  [so8-25x75-295]
U117  TMP102AIDRLT  [drl6-12x30]
sheet SH69 - POWER MONITOR 2
C1039  0.1uF  [c402-25]
C1040  0.1uF  [c402-25]
C1041  0.1uF  [c402-25]
C1042  0.1uF  [c402-25]
C1043  0.1uF  [c402-25]
C1044  0.1uF  [c402-25]
C1045  0.1uF  [c402-25]
C1046  0.1uF  [c402-25]
C1047  0.1uF  [c402-25]
C1065  0.1uF  [c402-25]
R1021  0.010  [r1206-40X70]
R1022  0.010  [r1206-40X70]
R1023  0.010  [r1206-40X70]
R1024  0.010  [r1210-70x102]
R1025  0.010  [r1206-40X70]
R1026  0.010  [r1210-70x102]
R1027  0.010  [r1206-40X70]
R1028  0.010  [r1206-40X70]
R1029  0.010  [r1206-40X70]
R1100  0.010  [r1206-40X70]
U1018  INA226AIDGSR  [dgs10-11x60]
U1019  INA226AIDGSR  [dgs10-11x60]
U1020  INA226AIDGSR  [dgs10-11x60]
U1021  INA226AIDGSR  [dgs10-11x60]
U1022  INA226AIDGSR  [dgs10-11x60]
U1023  INA226AIDGSR  [dgs10-11x60]
U1024  INA226AIDGSR  [dgs10-11x60]
U1025  INA226AIDGSR  [dgs10-11x60]
U1026  INA226AIDGSR  [dgs10-11x60]
U1031  INA226AIDGSR  [dgs10-11x60]
sheet SH70 - DARA INTERFACE
C1096  0.1uF  [c402-25]
J1003  AXT340124  [conn-axt40]
J1006  FH12A-40S-0.5SH(55)  [fh12-40-sh]
Q2026  BSS138  [SOT23-28X44-GSD]
R1142  10K  [r201-6p6spc]
R1143  10K  [r201-6p6spc]
R1144  0  [r201-6p6spc]
R1145  0  [r201-6p6spc]
R9355  1K  [r402-25]
R9356  10K  [r201-6p6spc]
R9359  1K  [r201-6p6spc]
R9360  1K  [r201-6p6spc]
R9361  1K  [r201-6p6spc]
R9362  1K  [r201-6p6spc]
R9363  1K  [r201-6p6spc]
R9364  1K  [r201-6p6spc]
R9365  0  [r201-6p6spc]
RU118  SN74CBTLV3257PW  [tssop16-14x70]

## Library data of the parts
C692 = CAP_NP_1: Part #: 101587-1100R
R235 R248 R259 R261 R510 R512 R614 R641 R651 R657 R718 R724 R1047 R1048 R1051 R1052 R1104 R1112 R1144 R1145 R9365 = R: Part #: 103158-0001R
R258 R658 = R: Part #: 103158-2200R
R233 R240 R268 R270 R618 R624 = R: Part #: 101370-2202R
R755 = R: Part #: 101370-1003R
R264 R776 R777 R1049 R1050 R1053 R1054 = R: Part #: R0201-NOPOP
U120 U121 = SN74LVC1G125_0: Part #: 101057-0126R
TP37 = TP_0: Part #: TP-18RD8-NO-POP
C439 C511 = CAP_NP: Part #: 103367-1102R
C440 = CAP_NP: Part #: 102963-0101R
C451 C510 = CAP_NP: Part #: 103241-1101R
C486 C489 = CAP_NP: Part #: 103241-1100R
R499 R500 R506 R508 R509 R511 = R0402-22: Part #: 103158-0001R
U52 = J6ECO_RevC_0: Part #: 104492-0002R-TI
C85 C98 C308 C322 C383 C428 = CAP: Part #: 101587-1100R
C129 C135 C296 C297 C323 C488 C1039-C1047 C1065 C1074 C1075 C1096 = CAP_NP: Part #: 101587-1100R
R246 R265 R458 R469 R622 R1108 R1142 R1143 R9356 = R: Part #: 103158-1003R
RU33 RU88 RU94 = SN74CBT16214DGGR_0: Part #: 102513-0001R
U22 U106 U1035 U1036 = SN74LVC1GU04_1: Part #: 101057-0004R
RU89 RU111 RU113 RU116 RU118 = SN74CBT3257PW_0: Part #: 101670-0001R
RU95 RU99 = SN74CBT16212DGGR_0: Part #: 102693-0001R
C315 = CAP_NP_2: Part #: 101587-1100R
RU29 = SN74LVC1G125: Part #: 101689-0125R
RU49 = 74PCT245_3: Part #: 101659-0001R; SD PCB Footprint: PSOP20PW
RU103 = 74PCT245_3: Part #: 101659-0001R
C513 C523 = CAP_.1_uF_10%_0603: Part #: 101587-1100R
R573-R575 R629 = R: Part #: R0402-NOPOP
R576 R578 R625 = R_1: Part #: 101370-0001R
R577 = R: Part #: r0402-nopop
U105 = 24WC256: Part #: 102235-0001R
U117 = TMP102AIDRLT: Part #: 104192-0001R
R1021-R1029 R1100 = R: Part #: 102598-0001R
U1018-U1026 U1031 = INA220IDCN_2: Part #: 103928-0001R
J1003 = CONN_AXT340124_40PINS_SMT_X: Part #: 104610-0040R
J1006 = HEADER_40_0: Part #: 101488-0040R
Q2026 = MOSFET_N_1: Part #: 100680-0001R
R9355 = R_2: Part #: 101370-1002R
R9359-R9364 = R_1: Part #: 103158-1002R

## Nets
GND: C85.2 C98.2 C129.2 C135.2 C296.2 C297.2 C308.2 C315.2 C322.2 C323.2 C383.2 C428.2 C439.2 C440.2 C451.2 C486.2 C488.2 C489.2 C510.2 C511.2 C513.1 C523.1 C692.2 C1039.1 C1040.1 C1041.1 C1042.1 C1043.1 C1044.1 C1045.1 C1046.1 C1047.1 C1065.1 C1074.2 C1075.2 C1096.2 J1003.41 J1003.42 J1003.43 J1003.44 J1006.7 J1006.16 J1006.25 J1006.34 J1006.40 Q2026.S R265.2 R574.2 R576.2 R578.2 R625.2 R718.1 R724.2 R1104.1 R1112.1 R9356.2 RU29.1(OE) RU29.3(GND) RU33.8(GND.1) RU33.19(GND.2) RU33.38(GND.3) RU33.49(GND.4) RU49.10(GND) RU49.19(~{OE}) RU88.8(GND.1) RU88.19(GND.2) RU88.38(GND.3) RU88.49(GND.4) RU89.8(GND) RU89.15(~{OE}) RU94.8(GND.1) RU94.19(GND.2) RU94.38(GND.3) RU94.49(GND.4) RU95.8(GND.1) RU95.19(GND.2) RU95.38(GND.3) RU95.49(GND.4) RU95.55(S2) RU99.8(GND.1) RU99.19(GND.2) RU99.38(GND.3) RU99.49(GND.4) RU99.55(S2) RU103.10(GND) RU103.19(~{OE}) RU111.8(GND) RU111.15(~{OE}) RU113.8(GND) RU113.9(3A) RU113.12(4A) RU113.15(~{OE}) RU116.8(GND) RU116.15(~{OE}) RU118.8(GND) RU118.9(3A) RU118.12(4A) U22.3(GND) U52.AA11(VSSA_USB.2) U52.AB11(VSSA_USB.1) U52.AD10(VSSA_USB3) U105.4(VSS) U106.3(GND) U117.2(GND) U120.3(GND) U121.3(GND) U1018.1(A1) U1018.2(A0) U1018.7(GND) U1019.2(A0) U1019.7(GND) U1020.1(A1) U1020.7(GND) U1021.7(GND) U1022.1(A1) U1022.7(GND) U1023.7(GND) U1024.1(A1) U1024.7(GND) U1025.2(A0) U1025.7(GND) U1026.7(GND) U1031.7(GND) U1035.3(GND) U1036.3(GND) ; also on sheet 3 5 7 10 11 12 13 14 15 16 17 18 20 21 22 23 24 25 26 27 28 29 30 31 32 33 34 35 36 37 38 39 40 41 42 43 44 45 46 47 48 49 50 51 52 53 54 55 56 57 70 71
VCCA_IN: R1029.2 U1026.9(VIN-) ; also on sheet 56
VDDA_1V8_PHY2: C510.1 R1100.2 U52.W14(VDDA_USB3) U1031.9(VIN-) ; also on sheet 7 71
VIN1A_CLK0: RU33.28(12B3) ; also on sheet 50
VIN1A_D0: RU94.10(4B3) ; also on sheet 50
VIN1A_D1: RU94.7(3B3) ; also on sheet 50
VIN1A_D2: RU94.5(2B3) ; also on sheet 50
VIN1A_D3: RU94.3(1B3) ; also on sheet 50
VIN1A_D4: RU88.28(12B3) ; also on sheet 50
VIN1A_D5: RU88.26(11B3) ; also on sheet 50
VIN1A_D6: RU88.24(10B3) ; also on sheet 50
VIN1A_D7: RU88.22(9B3) ; also on sheet 50
VIN1A_D8: RU88.20(8B3) ; also on sheet 50
VIN1A_D9: RU88.16(7B3) ; also on sheet 50
VIN1A_D10: RU88.14(6B3) ; also on sheet 50
VIN1A_D11: RU88.12(5B3) ; also on sheet 50
VIN1A_D12: RU88.10(4B3) ; also on sheet 50
VIN1A_D13: RU88.7(3B3) ; also on sheet 50
VIN1A_D14: RU88.5(2B3) ; also on sheet 50
VIN1A_D15: RU88.3(1B3) ; also on sheet 50
VIN1A_D16: RU94.12(5B3) ; also on sheet 50
VIN1A_D17: RU94.14(6B3) ; also on sheet 50
VIN1A_D18: RU94.16(7B3) ; also on sheet 50
VIN1A_D19: RU94.20(8B3) ; also on sheet 50
VIN1A_D20: RU94.22(9B3) ; also on sheet 50
VIN1A_D21: RU94.24(10B3) ; also on sheet 50
VIN1A_D22: RU94.26(11B3) ; also on sheet 50
VIN1A_D23: RU94.28(12B3) ; also on sheet 50
VIN1A_DE0: RU33.7(3B3) ; also on sheet 50
VIN1A_HSYNC0: RU33.3(1B3) ; also on sheet 50
VIN1A_VSYNC0: RU33.5(2B3) ; also on sheet 50
VIN2A_MDIO_D: RU116.5(2B1) ; also on sheet 25
VIN2A_MDIO_MCLK: RU116.2(1B1) ; also on sheet 25
VIN6_SEL_S0: R622.2 RU99.1(S0) U106.2(I) ; also on sheet 42
VIN[4]B_CLK1: RU89.2(1B1) ; also on sheet 49
VIN[4]B_D[0]: RU89.5(2B1) ; also on sheet 49
VIN[4]B_D[1]: RU89.14(4B1) ; also on sheet 49
VIN[4]B_D[2]: RU89.11(3B1) ; also on sheet 49
VIN[4]B_D[3]: RU95.29(12B2) ; also on sheet 49
VIN[4]B_D[4]: RU95.31(11B2) ; also on sheet 49
VIN[4]B_D[5]: RU95.53(1B2) ; also on sheet 49
VIN[4]B_D[6]: RU95.51(2B2) ; also on sheet 49
VIN[4]B_D[7]: RU95.42(6B2) ; also on sheet 49
VIN[4]B_HSYNC1: RU95.35(9B2) ; also on sheet 49
VIN[4]B_VSYNC1: RU95.37(8B2) ; also on sheet 49
VIN[6]A_D[0]: RU99.47(4B1) ; also on sheet 50
VIN[6]A_D[1]: RU99.50(3B1) ; also on sheet 50
VIN[6]A_D[2]: RU99.52(2B1) ; also on sheet 50
VIN[6]A_D[3]: RU99.54(1B1) ; also on sheet 50
VIN[6]A_D[7]: RU99.45(5B1) ; also on sheet 50
VIN[6]A_D[8]: RU99.43(6B1) ; also on sheet 50
VIN[6]A_D[9]: RU99.41(7B1) ; also on sheet 50
VIN[6]A_D[10]: RU99.39(8B1) ; also on sheet 50
VIN[6]A_D[11]: RU99.36(9B1) ; also on sheet 50
VIN[6]A_HSYNC: RU99.32(11B1) ; also on sheet 50
VIN[6]A_VSYNC: RU99.34(10B1) ; also on sheet 50
AIC_MCA3_ACLKX: RU99.53(1B2) ; also on sheet 34
AIC_MCA3_AFSX: RU99.51(2B2) ; also on sheet 34
AIC_MCA3_AXR0: RU99.48(3B2) ; also on sheet 34
AIC_MCA3_AXR1: RU99.46(4B2) ; also on sheet 34
C_EMAC[0]_RXC: RU95.2(1A1) U52.U5(RGMII0_RXC/rmii1_txen/mii0_txclk/VIN2a_d[5]/VIN1b_d[5]/usb3_ulpi_d2/pr1_mii_mt0_clk/pr2_pru1_pru_r31[11]/pr2_pru1_pru_r30[11]/)
C_EMAC[0]_RXCTL: RU95.4(2A1) U52.V5(RGMII0_RXCTL/rmii1_txd1/mii0_txd[3]/VIN2a_d[6]/VIN1b_d[6]/usb3_ulpi_d3/pr1_mii0_txd3/pr2_pru1_pru_r31[12]/pr2_pru1_pru_r30[12])
C_EMAC[0]_RXD0: RU95.6(3A1) U52.W2(RGMII0_RXD0/rmii0_txd0/mii0_txd[0]/VIN2a_fld0/VIN1b_fld1/usb3_ulpi_d7/pr1_mii0_txd0/pr2_pru1_pru_r31[16]/pr2_pru1_pru_r30[16]/)
C_EMAC[0]_RXD1: RU95.9(4A1) U52.Y2(RGMII0_RXD1/rmii0_txd1/mii0_txd[1]/VIN2a_d[9]/usb3_ulpi_d6/pr1_mii0_txd1/pr2_pru1_pru_r31[15]/pr2_pru1_pru_r30[15]/gpio5_30)
C_EMAC[0]_RXD2: RU95.11(5A1) U52.V3(RGMII0_RXD2/rmii0_txen/mii0_txen/VIN2a_d[8]/usb3_ulpi_d5/pr1_mii0_txen/pr2_pru1_pru_r31[14]/pr2_pru1_pru_r30[14]/gpio5_29)
C_EMAC[0]_RXD3: RU95.13(6A1) U52.V4(RGMII0_RXD3/rmii1_txd0/mii0_txd[2]/VIN2a_d[7]/VIN1b_d[7]/usb3_ulpi_d4/pr1_mii0_txd2/pr2_pru1_pru_r31[13]/pr2_pru1_pru_r30[13]/)
C_EMAC[0]_TXC: R511.2 RU95.27(12A1)
C_EMAC[0]_TXCTL: R509.2 RU95.25(11A1)
C_EMAC[0]_TXD0: R499.2 RU95.15(7A1)
C_EMAC[0]_TXD1: R500.2 RU95.18(8A1)
C_EMAC[0]_TXD2: R506.2 RU95.21(9A1)
C_EMAC[0]_TXD3: R508.2 RU95.23(10A1)
C_GPIO6_14: RU113.4(1A) U52.E21(GPIO6_14/MCASP1_axr[8]/dcan2_tx/uart10_rxd/VOUT2_hsync/VIN2a_hsync0/i2c3_sda/timer1/gpio6_14)
C_GPIO6_15: RU113.7(2A) U52.F20(GPIO6_15/MCASP1_axr[9]/dcan2_rx/uart10_txd/VOUT2_vsync/VIN2a_vsync0/i2c3_scl/timer2/gpio6_15)
C_GPMC_A0: RU94.11(5A) ; also on sheet 4 24
C_GPMC_A1: RU94.13(6A) ; also on sheet 4
C_GPMC_A2: RU94.15(7A) ; also on sheet 4
C_GPMC_A3: RU94.18(8A) ; also on sheet 4
C_GPMC_A4: RU94.21(9A) ; also on sheet 4
C_GPMC_A5: RU94.23(10A) ; also on sheet 4
C_GPMC_A6: RU94.25(11A) ; also on sheet 4
C_GPMC_A7: RU94.27(12A) ; also on sheet 4
C_GPMC_A8: RU33.2(1A) ; also on sheet 4
C_GPMC_A9: RU33.4(2A) ; also on sheet 4
C_GPMC_A10: RU33.6(3A) ; also on sheet 4
C_GPMC_A11: RU33.9(4A) ; also on sheet 4
C_GPMC_A12: RU33.11(5A) ; also on sheet 4
C_GPMC_D00: RU94.9(4A) ; also on sheet 4
C_GPMC_D01: RU94.6(3A) ; also on sheet 4
C_GPMC_D02: RU94.4(2A) ; also on sheet 4
C_GPMC_D03: RU94.2(1A) ; also on sheet 4
C_GPMC_D04: RU88.27(12A) ; also on sheet 4
C_GPMC_D05: RU88.25(11A) ; also on sheet 4
C_GPMC_D06: RU88.23(10A) ; also on sheet 4
C_GPMC_D07: RU88.21(9A) ; also on sheet 4
C_GPMC_D08: RU88.18(8A) ; also on sheet 4
C_GPMC_D09: RU88.15(7A) ; also on sheet 4
C_GPMC_D10: RU88.13(6A) ; also on sheet 4
C_GPMC_D11: RU88.11(5A) ; also on sheet 4
C_GPMC_D12: RU88.9(4A) ; also on sheet 4
C_GPMC_D13: RU88.6(3A) ; also on sheet 4
C_GPMC_D14: RU88.4(2A) ; also on sheet 4
C_GPMC_D15: RU88.2(1A) ; also on sheet 4
C_GPMC_nCS3: RU33.27(12A) ; also on sheet 4 24
C_MCA1_ACLKX: R1054.2 ; also on sheet 2
C_MCA1_AFSX: R1053.2 ; also on sheet 2
C_MCA1_AXR0: R1049.2 R1052.2 ; also on sheet 2
C_MCA1_AXR1: R1050.2 R1051.2 ; also on sheet 2
C_MCA2_ACLKX: RU99.11(5A1) ; also on sheet 2
C_MCA2_AFSX: RU49.8(A7) ; also on sheet 2
C_MCA2_AXR0: RU103.2(A1) ; also on sheet 2
C_MCA2_AXR1: RU103.3(A2) ; also on sheet 2
C_MCA2_AXR2: RU103.4(A3) ; also on sheet 2
C_MCA2_AXR3: RU103.5(A4) ; also on sheet 2
C_MCA2_AXR4: RU103.6(A5) ; also on sheet 2
C_MCA2_AXR5: RU103.7(A6) ; also on sheet 2
C_MCA2_AXR6: RU103.8(A7) ; also on sheet 2
C_MCA2_AXR7: RU103.9(A8) ; also on sheet 2
C_MCA3_ACLKX: RU99.2(1A1) ; also on sheet 2
C_MCA3_AFSX: RU99.4(2A1) ; also on sheet 2
C_MCA3_AXR0: RU99.6(3A1) ; also on sheet 2
C_MCA3_AXR1: RU99.9(4A1) ; also on sheet 2
C_MCA6_AXR0: RU49.4(A3) ; also on sheet 2
C_MCA6_AXR1: RU49.5(A4) ; also on sheet 2
C_MCA6_CLKX: RU49.3(A2) ; also on sheet 2
C_MCA6_FSX: RU49.2(A1) ; also on sheet 2
C_MCA7_AXR0: RU99.21(9A1) ; also on sheet 2
C_MCA7_AXR1: RU99.18(8A1) ; also on sheet 2
C_MCA7_CLKX: RU99.15(7A1) ; also on sheet 2
C_MCA7_FSX: RU99.13(6A1) ; also on sheet 2
C_MDIO_MDCLK: RU89.4(1A) U52.V1(MDIO_MCLK/uart3_rtsn/mii0_col/VIN2a_clk0/VIN1b_clk1/pr1_mii0_col/pr2_pru1_pru_r31[0]/pr2_pru1_pru_r30[0]/gpio5_15)
C_MDIO_MDIO: RU89.7(2A) U52.U4(MDIO_D/uart3_ctsn/mii0_txer/VIN2a_d[0]/VIN1b_d[0]/pr1_mii0_rxlink/pr2_pru1_pru_r31[1]/pr2_pru1_pru_r30[1]/gpio5_16)
C_SPI2_CS0n: RU111.12(4A) U52.B24(SPI2_CS0/uart3_rtsn/uart5_txd/gpio7_17)
C_SPI2_MISO: RU111.7(2A) U52.B22(SPI2_D1/uart3_txd/gpio7_15)
C_SPI2_MOSI: RU111.9(3A) U52.G17(SPI2_D0/uart3_ctsn/uart5_rxd/gpio7_16)
C_SPI2_SCLK: R261.1 RU111.4(1A)
C_UART3_RXD: RU89.12(4A) U52.V2(UART3_RXD/rmii1_crs/mii0_rxdv/VIN2a_d[1]/VIN1b_d[1]/spi3_sclk/pr1_mii0_rxdv/pr2_pru1_pru_r31[3]/pr2_pru1_pru_r30[3]/gpio5_18)
C_UART3_TXD: RU89.9(3A) U52.Y1(UART3_TXD/rmii1_rxer/mii0_rxclk/VIN2a_d[2]/VIN1b_d[2]/spi3_d[1]/spi4_cs[1]/pr1_mii_mr0_clk/pr2_pru1_pru_r31[4]/pr2_pru1_pru_r3)
C_XREF_CLK1: RU29.2(I) ; also on sheet 2
CAM_SPI[1]_CS[0]n: R248.1 ; also on sheet 40
CAM_SPI[1]_MISO: R235.1 ; also on sheet 40
CAM_SPI[1]_MOSI: R259.1 ; also on sheet 40
CAM_SPI[1]_SCLK: R658.1 ; also on sheet 40
CORE_VDD: J1003.8 ; also on sheet 11 17 56 57
DCAN1_TX: U52.G20(DCAN1_TX/uart8_rxd/mmc2_sdcd/sata2_led/hdmi1_hpd/gpio1_14) ; also on sheet 41
DCAN2_RX: RU113.6(2B2) ; also on sheet 41
DCAN2_TX: RU113.3(1B2) ; also on sheet 41
EMAC[0]_RXC: RU95.54(1B1) ; also on sheet 47
EMAC[0]_RXCTL: RU95.52(2B1) ; also on sheet 47
EMAC[0]_RXD0: RU95.50(3B1) ; also on sheet 47
EMAC[0]_RXD1: RU95.47(4B1) ; also on sheet 47
EMAC[0]_RXD2: RU95.45(5B1) ; also on sheet 47
EMAC[0]_RXD3: RU95.43(6B1) ; also on sheet 47
EMAC[0]_TXC: RU95.30(12B1) ; also on sheet 47
EMAC[0]_TXCTL: RU95.32(11B1) ; also on sheet 47
EMAC[0]_TXD0: RU95.41(7B1) ; also on sheet 47
EMAC[0]_TXD1: RU95.39(8B1) ; also on sheet 47
EMAC[0]_TXD2: RU95.36(9B1) ; also on sheet 47
EMAC[0]_TXD3: RU95.34(10B1) ; also on sheet 47
ENET_INTSn: U52.F21(GPIO6_16/MCASP1_axr[10]/VOUT2_fld/VIN2a_fld0/clkout1/timer3/gpio6_16) ; also on sheet 46
EVM_1V8: J1003.16 ; also on sheet 29 37 40 44 45 46 50 55 57
EVM_3V3: C98.1 C129.1 C135.1 C296.1 C297.1 C315.1 C323.1 C383.1 C428.1 C488.1 C513.2 C523.2 C692.1 C1074.1 C1075.1 C1096.1 J1006.1 J1006.2 J1006.3 R233.1 R240.1 R246.1 R264.1 R268.1 R270.1 R458.1 R469.1 R573.1 R575.1 R577.1 R618.1 R622.1 R624.1 R629.1 R755.1 R1026.2 R1108.2 R1142.1 R1143.1 RU29.5(VCC) RU49.20(VCC) RU89.16(VCC) RU95.17(VCC.1) RU99.17(VCC.1) RU103.20(VCC) RU111.16(VCC) RU113.16(VCC) RU116.16(VCC) RU118.16(VCC) U22.5(VCC) U105.8(VCC) U106.5(VCC) U117.5(V+) U120.5(VCC) U121.5(VCC) U1023.9(VIN-) U1035.5(VCC) U1036.5(VCC) ; also on sheet 3 4 10 11 24 25 26 27 28 29 30 31 32 33 34 35 36 37 38 39 40 42 43 44 45 46 47 48 49 50 51 55 56 70
EVM_5V0: C85.1 C308.1 C322.1 R1024.2 RU33.17(VCC.1) RU88.17(VCC.1) RU94.17(VCC.1) U1021.9(VIN-) ; also on sheet 25 30 31 36 37 38 40 41 45 50 54 55
EVM_12V: R1028.2 U1025.9(VIN-) ; also on sheet 3 36 50 53 54
EVM_VDD_DDR: J1003.28 ; also on sheet 20 21 22 23 55 56 57
GP5[0]: R9365.2 ; also on sheet 2 50
GP5[17]: U52.U3(RMII_MHZ_50_CLK/VIN2a_d[11]/pr2_pru1_pru_r31[2]/pr2_pru1_pru_r30[2]/gpio5_17) ; also on sheet 50
GP5[22]: RU95.33(10B2) ; also on sheet 49
GP5[25]: RU95.40(7B2) ; also on sheet 49
GP5[29]: RU95.44(5B2) ; also on sheet 49
GP5[30]: RU95.46(4B2) ; also on sheet 49
GP5[31]: RU95.48(3B2) ; also on sheet 49
GP6_[28]: U52.Y9(MMC1_SDWP/uart6_txd/i2c4_scl/gpio6_28) ; also on sheet 3
GPIO6[10]: U52.AC5(GPIO6_10/mdio_mclk/i2c3_sda/usb3_ulpi_d7/VIN2b_hsync1/VIN1a_clk0/ehrpwm2A/pr2_mii_mt1_clk/pr2_pru0_pru_r31[0]/pr2_pru0_pru_r30) ; also on sheet 51
GPIO6[11]: U52.AB4(GPIO6_11/mdio_d/i2c3_scl/usb3_ulpi_d6/VIN2b_vsync1/VIN1a_de0/ehrpwm2B/pr2_mii1_txen/pr2_pru0_pru_r31[1]/pr2_pru0_pru_r30[1]/gp) ; also on sheet 51
GPMC_A1: RU94.43(6B1) ; also on sheet 28
GPMC_A2: RU94.41(7B1) ; also on sheet 28
GPMC_A3: RU94.39(8B1) ; also on sheet 28
GPMC_A4: RU94.36(9B1) ; also on sheet 28
GPMC_A5: RU94.34(10B1) ; also on sheet 28
GPMC_A6: RU94.32(11B1) ; also on sheet 28
GPMC_A7: RU94.30(12B1) ; also on sheet 28
GPMC_A8: RU33.54(1B1) ; also on sheet 28
GPMC_A9: RU33.52(2B1) ; also on sheet 28
GPMC_A10: RU33.50(3B1) ; also on sheet 28
GPMC_A11: RU33.47(4B1) ; also on sheet 28
GPMC_A12: RU33.45(5B1) ; also on sheet 28
GPMC_D00: R9359.2 RU94.47(4B1) ; also on sheet 27 28 43
GPMC_D01: R9360.2 RU94.50(3B1) ; also on sheet 27 28 43
GPMC_D02: R9361.2 RU94.52(2B1) ; also on sheet 27 28 43
GPMC_D03: R9362.2 RU94.54(1B1) ; also on sheet 27 28 43
GPMC_D04: R9363.2 RU88.30(12B1) ; also on sheet 27 28 43
GPMC_D05: R9364.2 RU88.32(11B1) ; also on sheet 27 28 43
GPMC_D06: RU88.34(10B1) ; also on sheet 27 28 43
GPMC_D07: RU88.36(9B1) ; also on sheet 27 28 43
GPMC_D08: RU88.39(8B1) ; also on sheet 27 28 43
GPMC_D09: RU88.41(7B1) ; also on sheet 27 28 43
GPMC_D10: RU88.43(6B1) ; also on sheet 27 28 43
GPMC_D11: RU88.45(5B1) ; also on sheet 27 28 43
GPMC_D12: RU88.47(4B1) ; also on sheet 27 28 43
GPMC_D13: RU88.50(3B1) ; also on sheet 27 28 43
GPMC_D14: RU88.52(2B1) ; also on sheet 27 28 43
GPMC_D15: RU88.54(1B1) ; also on sheet 27 28 43
HDMI_CEC_A: U52.B20(SPI1_CS3/uart4_txd/mmc3_sdwp/spi2_cs[3]/dcan2_rx/mdio_d/hdmi1_cec/hdmi2_cec/gpio7_13) ; also on sheet 38
HDMI_DSCL: R1048.1 ; also on sheet 38
HDMI_DSDA: R1047.1 ; also on sheet 38
HDMI_HPD: U52.B21(SPI1_CS2/uart4_rxd/mmc3_sdcd/spi2_cs[2]/dcan2_tx/mdio_mclk/hdmi1_hpd/hdmi2_hpd/gpio7_12) ; also on sheet 38
I2C1_SCL: R618.2 U52.C20(I2C1_SCL) U105.6(SCL) U117.1(SCL) ; also on sheet 3 34 37 42 45 50 56
I2C1_SDA: R624.2 U52.C21(I2C1_SDA) U105.5(SDA) U117.6(SDA) ; also on sheet 3 34 37 42 45 50 56
I2C3_SCL: R270.2 R1144.2 RU113.5(2B1) ; also on sheet 49
I2C3_SDA: R268.2 R1145.2 RU113.2(1B1) ; also on sheet 49
I2C5_SCL: R233.2 R1051.1 R1053.1 ; also on sheet 39 40 42 51
I2C5_SDA: R240.2 R1052.1 R1054.1 ; also on sheet 39 40 42 51
I2C_EEPROM_WP: U105.7(WP) ; also on sheet 43
J6_VDD_1V8: J1003.20 ; also on sheet 3 11 13 14 56 57
J6_VDD_DDR: J1003.24 ; also on sheet 55 57
J6_VDD_GPU: J1003.32 ; also on sheet 17 56 57
J6_VDD_MPU: J1003.4 ; also on sheet 17 52 56 57
J6_VDDA_PHY: C486.1 C511.1 R1025.2 U52.AA13(VDDA_USB1) U52.AB12(VDDA_USB2) U1022.9(VIN-) ; also on sheet 16 71
J6_VDDA_PLL: R1022.2 U1019.9(VIN-) ; also on sheet 11 16
J6_VDDA_USB3V3: C439.1 C440.1 C451.1 C489.1 R1027.2 U52.AA12(VDDA33V_USB1) U52.Y12(VDDA33V_USB2) U1024.9(VIN-)
J6_VDDSHV5: J1003.12 R1023.2 U1020.9(VIN-) ; also on sheet 11 13 41
J6_VDDSHV8: R1021.2 U1018.9(VIN-) ; also on sheet 13 30
LDO1_OUT: R1021.1 U1018.8(VBUS) U1018.10(VIN+) ; also on sheet 56
LDO2_OUT: R1100.1 U1031.8(VBUS) U1031.10(VIN+) ; also on sheet 56
LDO3_OUT: R1025.1 U1022.8(VBUS) U1022.10(VIN+) ; also on sheet 56
LDO4_OUT: R1027.1 U1024.8(VBUS) U1024.10(VIN+) ; also on sheet 56
LDO5_OUT: R1022.1 U1019.8(VBUS) U1019.10(VIN+) ; also on sheet 56
MCA2_ACLKX: RU99.44(5B2) ; also on sheet 50
MCA2_AFSX: RU49.12(B7) ; also on sheet 50
MCA2_AXR0: RU103.18(B1) ; also on sheet 50
MCA2_AXR1: RU103.17(B2) ; also on sheet 50
MCA2_AXR2: RU103.16(B3) ; also on sheet 50
MCA2_AXR3: RU103.15(B4) ; also on sheet 50
MCA2_AXR4: RU103.14(B5) ; also on sheet 50
MCA2_AXR5: RU103.13(B6) ; also on sheet 50
MCA2_AXR6: RU103.12(B7) ; also on sheet 50
MCA2_AXR7: RU103.11(B8) ; also on sheet 50
MCA6_ACLKX: RU49.17(B2) ; also on sheet 50
MCA6_AFSX: RU49.18(B1) ; also on sheet 50
MCA6_AHCLKX: RU29.4(O) ; also on sheet 50
MCA6_AXR0: RU49.16(B3) ; also on sheet 50
MCA6_AXR1: RU49.15(B4) ; also on sheet 50
MCA7_AXR0: RU99.35(9B2) ; also on sheet 44
MCA7_AXR1: RU99.37(8B2) ; also on sheet 44
MCA7_CLKX: RU99.40(7B2) ; also on sheet 44
MCA7_FSX: RU99.42(6B2) ; also on sheet 44
MDIO_MDCLK: RU116.4(1A) ; also on sheet 46 47 48
MDIO_MDIO: RU116.7(2A) ; also on sheet 46 47 48
MMC1_CLK: R510.1 ; also on sheet 30
MMC1_CMD: U52.Y6(MMC1_CMD/gpio6_22) ; also on sheet 30
MMC1_DAT0: U52.AA6(MMC1_DAT0/gpio6_23) ; also on sheet 30
MMC1_DAT1: U52.Y4(MMC1_DAT1/gpio6_24) ; also on sheet 30
MMC1_DAT2: U52.AA5(MMC1_DAT2/gpio6_25) ; also on sheet 30
MMC1_DAT3: U52.Y3(MMC1_DAT3/gpio6_26) ; also on sheet 30
MMC1_SD_CD: U52.W7(MMC1_SDCD/uart6_rxd/i2c4_sda/gpio6_27) ; also on sheet 30
MMC3_CLK: R512.1 ; also on sheet 51
MMC3_CMD: U52.AC4(MMC3_CMD/spi3_sclk/usb3_ulpi_d4/VIN2b_d[6]/VIN1a_d[6]/eCAP2_in_PWM2_out/pr2_mii1_txd2/pr2_pru0_pru_r31[3]/pr2_pru0_pru_r30[3]/) ; also on sheet 51
MMC3_DAT0: U52.AC7(MMC3_DAT0/spi3_d[1]/uart5_rxd/usb3_ulpi_d3/VIN2b_d[5]/VIN1a_d[5]/eQEP3A_in/pr2_mii1_txd1/pr2_pru0_pru_r31[4]/pr2_pru0_pru_r30[) ; also on sheet 51
MMC3_DAT1: U52.AC6(MMC3_DAT1/spi3_d[0]/uart5_txd/usb3_ulpi_d2/VIN2b_d[4]/VIN1a_d[4]/eQEP3B_in/pr2_mii1_txd0/pr2_pru0_pru_r31[5]/pr2_pru0_pru_r30[) ; also on sheet 51
MMC3_DAT2: U52.AC9(MMC3_DAT2/spi3_cs[0]/uart5_ctsn/usb3_ulpi_d1/VIN2b_d[3]/VIN1a_d[3]/eQEP3_index/pr2_mii_mr1_clk/pr2_pru0_pru_r31[6]/pr2_pru0_pr) ; also on sheet 51
MMC3_DAT3: U52.AC3(MMC3_DAT3/spi3_cs[1]/uart5_rtsn/usb3_ulpi_d0/VIN2b_d[2]/VIN1a_d[2]/eQEP3_strobe/pr2_mii1_rxdv/pr2_pru0_pru_r31[7]/pr2_pru0_pru) ; also on sheet 51
MMC3_DAT4: U52.AC8(MMC3_DAT4/spi4_sclk/uart10_rxd/usb3_ulpi_nxt/VIN2b_d[1]/VIN1a_d[1]/ehrpwm3A/pr2_mii1_rxd3/pr2_pru0_pru_r31[8]/pr2_pru0_pru_r30) ; also on sheet 51
MMC3_DAT5: U52.AD6(MMC3_DAT5/spi4_d[1]/uart10_txd/usb3_ulpi_dir/VIN2b_d[0]/VIN1a_d[0]/ehrpwm3B/pr2_mii1_rxd2/pr2_pru0_pru_r31[9]/pr2_pru0_pru_r30) ; also on sheet 51
MMC3_DAT6: U52.AB8(MMC3_DAT6/spi4_d[0]/uart10_ctsn/usb3_ulpi_stp/VIN2b_de1/VIN1a_hsync0/ehrpwm3_tripzone_input/pr2_mii1_rxd1/pr2_pru0_pru_r31[10]) ; also on sheet 51
MMC3_DAT7: U52.AB5(MMC3_DAT7/spi4_cs[0]/uart10_rtsn/usb3_ulpi_clk/VIN2b_clk1/VIN1a_vsync0/eCAP3_in_PWM3_out/pr2_mii1_rxd0/pr2_pru0_pru_r31[11]/pr) ; also on sheet 51
MMC4_CLK: R651.1 ; also on sheet 44
MMC4_CMD: U52.C27(UART1_RTSN/uart9_txd/mmc4_cmd/gpio7_25) ; also on sheet 44
MMC4_DAT0: U52.D28(UART2_RXD/uart3_ctsn/uart3_rctx/mmc4_dat[0]/uart2_rxd/uart1_dcdn/gpio7_26) ; also on sheet 44
MMC4_DAT1: U52.D26(UART2_TXD/uart3_rtsn/uart3_sd/mmc4_dat[1]/uart2_txd/uart1_dsrn/gpio7_27) ; also on sheet 44
MMC4_DAT2: R776.2 U52.D27(UART2_CTSN/uart3_irrx/mmc4_dat[2]/uart10_rxd/uart1_dtrn/gpio1_16) ; also on sheet 44
MMC4_DAT3: R777.2 U52.C28(UART2_RTSN/uart3_txd/uart3_irtx/mmc4_dat[3]/uart10_txd/uart1_rin/gpio1_17) ; also on sheet 44
PB_ON: R9355.1 ; also on sheet 53 54
PM1_SCL: J1006.36 RU118.2(1B1) ; also on sheet 56 57
PM1_SDA: J1006.38 RU118.5(2B1) ; also on sheet 56 57
PM2_SCL: J1006.37 RU118.3(1B2) U1018.5(SCL) U1019.5(SCL) U1020.5(SCL) U1021.5(SCL) U1022.5(SCL) U1023.5(SCL) U1024.2(A0) U1024.5(SCL) U1025.5(SCL) U1026.2(A0) U1026.5(SCL) U1031.5(SCL) ; also on sheet 56
PM2_SDA: J1006.39 RU118.6(2B2) U1018.4(SDA) U1019.4(SDA) U1020.4(SDA) U1021.4(SDA) U1022.2(A0) U1022.4(SDA) U1023.2(A0) U1023.4(SDA) U1024.4(SDA) U1025.1(A1) U1025.4(SDA) U1026.4(SDA) U1031.1(A1) U1031.4(SDA) ; also on sheet 56
PM_BRD_PWR_OFF: J1006.26 Q2026.G R9356.1
PM_OEn: R1142.2 RU118.15(~{OE}) ; also on sheet 42
PM_PORn: J1006.27 ; also on sheet 52
PM_RESETn: J1006.28 ; also on sheet 52
PM_SEL: R1143.2 RU118.1(S) ; also on sheet 42
RSTOUTn: J1006.29 ; also on sheet 3 11 26 28 29 34 35 40 56
SEL_ENET_MUX_S0: R469.2 RU89.1(S) RU95.1(S0) RU116.1(S) U1035.2(I) ; also on sheet 42
SEL_GPMC_AD_VID_S0: R458.2 RU33.1(S0) RU88.1(S0) RU94.1(S0) U22.2(I) ; also on sheet 42
SEL_GPMC_AD_VID_S1: RU33.56(S1) RU88.56(S1) RU94.56(S1) U22.4(O)
SEL_GPMC_AD_VID_S2: R1108.1 U1036.2(I) ; also on sheet 42
SEL_GPMC_AD_VID_S2n: RU33.55(S2) RU88.55(S2) RU94.55(S2) U1036.4(O)
SEL_I2C3_CAN2: R264.2 R265.1 RU113.1(S) ; also on sheet 42
SEL_UART3_SPI2: R246.2 RU111.1(S) ; also on sheet 42
SMPS1: J1003.2 ; also on sheet 56 57
SMPS2: J1003.6 ; also on sheet 56 57
SMPS3: J1003.30 ; also on sheet 56 57
SMPS4: J1003.14 J1003.18 ; also on sheet 56 57
SMPS5: J1003.22 J1003.26 ; also on sheet 56 57
SPI[1]_CS[0]n: R641.1 ; also on sheet 51
SPI[1]_CS[1]n: U52.A22(SPI1_CS1/sata2_led/sata1_led/spi2_cs[1]/gpio7_11) ; also on sheet 51 55
SPI[1]_MISO: R614.1 ; also on sheet 51
SPI[1]_MOSI: R657.1 ; also on sheet 51
SPI[1]_SCLK: R258.1 ; also on sheet 51
SPI[2]_CS[0]n: RU111.13(4B2) ; also on sheet 51
SPI[2]_MISO: RU111.6(2B2) ; also on sheet 51
SPI[2]_MOSI: RU111.10(3B2) ; also on sheet 51
SPI[2]_SCLK: RU111.3(1B2) ; also on sheet 51
SW_VSYS_3V3: J1003.10 R1023.1 R1026.1 U1020.8(VBUS) U1020.10(VIN+) U1023.8(VBUS) U1023.10(VIN+) ; also on sheet 55
TMP102_ALERT: U117.3(ALERT) ; also on sheet 42
TS_LCD_IRQ: U52.G19(DCAN1_RX/uart8_txd/mmc2_sdwp/sata1_led/hdmi1_cec/gpio1_15) ; also on sheet 37
UART1_RXD: U52.B27(UART1_RXD/mmc4_sdcd/gpio7_22) ; also on sheet 33
UART1_TXD: U52.C26(UART1_TXD/mmc4_sdwp/gpio7_23) ; also on sheet 33
UART3_CTS: RU111.11(3B1) ; also on sheet 44
UART3_RTS: RU111.14(4B1) ; also on sheet 44
UART3_RXD: RU111.2(1B1) ; also on sheet 44
UART3_RXD_BOOT: R776.1 ; also on sheet 33
UART3_TXD: RU111.5(2B1) ; also on sheet 44
UART3_TXD_BOOT: R777.1 ; also on sheet 33
USB1_DM: U52.AC12(USB1_DM) ; also on sheet 32
USB1_DP: U52.AD12(USB1_DP) ; also on sheet 32
USB1_DRV_VBUS: U52.AB10(USB1_DRVVBUS) ; also on sheet 31
USB2_DM: U52.AF11(USB2_DM) ; also on sheet 32
USB2_DP: U52.AE11(USB2_DP) ; also on sheet 32
USB2_DRV_VBUS: U52.AC10(USB2_DRVVBUS) ; also on sheet 31
USB_RXN0: U52.AF12(USB_RXN0) ; also on sheet 32
USB_RXP0: U52.AE12(USB_RXP0) ; also on sheet 32
USB_TXN0: U52.AC11(USB_TXN0) ; also on sheet 32
USB_TXP0: U52.AD11(USB_TXP0) ; also on sheet 32
VOUT3B_CLK: RU33.29(12B2) ; also on sheet 39
VOUT3B_D0: RU94.46(4B2) ; also on sheet 39
VOUT3B_D1: RU94.48(3B2) ; also on sheet 39
VOUT3B_D2: RU94.51(2B2) ; also on sheet 39
VOUT3B_D3: RU94.53(1B2) ; also on sheet 39
VOUT3B_D4: RU88.29(12B2) ; also on sheet 39
VOUT3B_D5: RU88.31(11B2) ; also on sheet 39
VOUT3B_D6: RU88.33(10B2) ; also on sheet 39
VOUT3B_D7: RU88.35(9B2) ; also on sheet 39
VOUT3B_D8: RU88.37(8B2) ; also on sheet 39
VOUT3B_D9: RU88.40(7B2) ; also on sheet 39
VOUT3B_D10: RU88.42(6B2) ; also on sheet 39
VOUT3B_D11: RU88.44(5B2) ; also on sheet 39
VOUT3B_D12: RU88.46(4B2) ; also on sheet 39
VOUT3B_D13: RU88.48(3B2) ; also on sheet 39
VOUT3B_D14: RU88.51(2B2) ; also on sheet 39
VOUT3B_D15: RU88.53(1B2) ; also on sheet 39
VOUT3B_D16: RU94.44(5B2) ; also on sheet 39
VOUT3B_D17: RU94.42(6B2) ; also on sheet 39
VOUT3B_D18: RU94.40(7B2) ; also on sheet 39
VOUT3B_D19: RU94.37(8B2) ; also on sheet 39
VOUT3B_D20: RU94.35(9B2) ; also on sheet 39
VOUT3B_D21: RU94.33(10B2) ; also on sheet 39
VOUT3B_D22: RU94.31(11B2) ; also on sheet 39
VOUT3B_D23: RU94.29(12B2) ; also on sheet 39
VOUT3B_DE: RU33.48(3B2) ; also on sheet 39
VOUT3B_HSYNC: RU33.53(1B2) ; also on sheet 39
VOUT3B_INTB: RU33.46(4B2) ; also on sheet 39
VOUT3B_VSYNC: RU33.51(2B2) ; also on sheet 39
VSYS_3V3: C1039.2 C1040.2 C1041.2 C1042.2 C1043.2 C1044.2 C1045.2 C1046.2 C1047.2 C1065.2 R1029.1 U1018.6(VS) U1019.1(A1) U1019.6(VS) U1020.2(A0) U1020.6(VS) U1021.1(A1) U1021.2(A0) U1021.6(VS) U1022.6(VS) U1023.1(A1) U1023.6(VS) U1024.6(VS) U1025.6(VS) U1026.1(A1) U1026.6(VS) U1026.8(VBUS) U1026.10(VIN+) U1031.2(A0) U1031.6(VS) ; also on sheet 11 23 36 46 52 54 55 56 57
VSYS_5V0: R1024.1 U1021.8(VBUS) U1021.10(VIN+) ; also on sheet 46 54 56
VSYS_12V0: R1028.1 U1025.8(VBUS) U1025.10(VIN+) ; also on sheet 53
N18148316: R718.2 RU33.10(4B3) RU33.12(5B3) RU33.13(6A) RU33.14(6B3) RU33.15(7A) RU33.16(7B3) RU33.18(8A) RU33.20(8B3) RU33.21(9A) RU33.22(9B3) RU33.23(10A) RU33.24(10B3) RU33.25(11A) RU33.26(11B3)
N18150546: R724.1 RU99.3(1A2) RU99.5(2A2) RU99.7(3A2) RU99.10(4A2) RU99.12(5A2) RU99.14(6A2) RU99.16(7A2) RU99.20(8A2) RU99.22(9A2) RU99.24(10A2) RU99.26(11A2) RU99.27(12A1) RU99.28(12A2)
N23575686: R248.2 R641.2 U52.A24(SPI1_CS0/gpio7_10)
N23575700: R261.2 U52.A26(SPI2_SCLK/uart3_rxd/gpio7_14)
N23575706: R235.2 R614.2 U52.F16(SPI1_D1/gpio7_8)
N23575710: R651.2 U52.E25(UART1_CTSN/uart9_rxd/mmc4_clk/gpio7_24)
N23575716: R259.2 R657.2 U52.B25(SPI1_D0/gpio7_9)
N23575750: R1047.2 U52.F17(I2C2_SCL/hdmi1_ddc_sda/hdmi2_ddc_sda)
N23575756: R1048.2 U52.C25(I2C2_SDA/hdmi1_ddc_scl/hdmi2_ddc_scl)
N23576463: R755.2 U120.1(OE) U121.1(OE)
N23576491: U52.A25(SPI1_SCLK/gpio7_7) U120.2(I) U121.2(I)
N23576511: R658.2 U120.4(O)
N23576513: R258.2 U121.4(O)
N23576753: R510.2 U52.W6(MMC1_CLK/gpio6_21)
N23576759: TP37.1 U52.Y5(MMC1_BIAS)
N23576767: R512.2 U52.AD4(MMC3_CLK/usb3_ulpi_d5/VIN2b_d[7]/VIN1a_d[7]/ehrpwm2_tripzone_input/pr2_mii1_txd3/pr2_pru0_pru_r31[2]/pr2_pru0_pru_r30[2]/gpio6)
N23577263: R511.1 U52.W9(RGMII0_TXC/uart3_ctsn/rmii1_rxd1/mii0_rxd[3]/VIN2a_d[3]/VIN1b_d[3]/usb3_ulpi_clk/spi3_d[0]/spi4_cs[2]/pr1_mii0_rxd3/pr2_pru1_p)
N23577265: R509.1 U52.V9(RGMII0_TXCTL/uart3_rtsn/rmii1_rxd0/mii0_rxd[2]/VIN2a_d[4]/VIN1b_d[4]/usb3_ulpi_stp/spi3_cs[0]/spi4_cs[3]/pr1_mii0_rxd2/pr2_pru)
N23577267: R508.1 U52.V7(RGMII0_TXD3/rmii0_crs/mii0_crs/VIN2a_de0/VIN1b_de1/usb3_ulpi_dir/spi4_sclk/uart4_rxd/pr1_mii0_crs/pr2_pru1_pru_r31[7]/pr2_pru1)
N23577269: R506.1 U52.U7(RGMII0_TXD2/rmii0_rxer/mii0_rxer/VIN2a_hsync0/VIN1b_hsync1/usb3_ulpi_nxt/spi4_d[1]/uart4_txd/pr1_mii0_rxer/pr2_pru1_pru_r31[8])
N23577271: R500.1 U52.V6(RGMII0_TXD1/rmii0_rxd1/mii0_rxd[1]/VIN2a_vsync0/VIN1b_vsync1/usb3_ulpi_d0/spi4_d[0]/uart4_ctsn/pr1_mii0_rxd1/pr2_pru1_pru_r31[)
N23577273: R499.1 U52.U6(RGMII0_TXD0/rmii0_rxd0/mii0_rxd[0]/VIN2a_d[10]/usb3_ulpi_d1/spi4_cs[0]/uart4_rtsn/pr1_mii0_rxd0/pr2_pru1_pru_r31[10]/pr2_pru1_)
N23583926: RU89.3(1B2) RU116.3(1B2)
N23583932: RU89.6(2B2) RU116.6(2B2)
N23756281: R1050.1 RU99.25(11A1)
N23756284: R1049.1 RU99.23(10A1)
N25590937: R1104.2 RU95.3(1A2) RU95.5(2A2) RU95.7(3A2) RU95.10(4A2) RU95.12(5A2) RU95.14(6A2) RU95.16(7A2) RU95.20(8A2) RU95.22(9A2) RU95.24(10A2) RU95.26(11A2) RU95.28(12A2)
N25595376: RU95.56(S1) U1035.4(O)
N25660136: R1112.2 RU116.9(3A) RU116.12(4A)
N25970375: J1006.8 R9359.1
N25970377: J1006.9 R9360.1
N25970379: J1006.10 R9361.1
N25970381: J1006.11 R9362.1
N25970383: J1006.12 R9363.1
N25970385: J1006.13 R9364.1
N25970890: J1006.32 R9365.1
N26039316: Q2026.D R9355.2
N26039507: R1144.1 RU118.4(1A)
N26039509: R1145.1 RU118.7(2A)
N29597106: R577.2 R578.1 U105.1(A0)
N29597110: R575.2 R576.1 U105.2(A1)
N29597116: R573.2 R574.1 U105.3(NC)
N29675465: R625.1 R629.2 U117.4(ADD0)
N33175207: RU99.56(S1) U106.4(O)

Not connected (* = marked no-connect by the designer): J1003 1 3 5 7 9 11 13 15 17 19 21 23 25 27 29 31 33 34 35 36 37 38 39 40; J1006 4 5 6 14 15 17 18 19 20 21 22 23 24 30 31 33 35 41 42; RU33 30(12B1) 31(11B2) 32(11B1) 33(10B2) 34(10B1) 35(9B2) 36(9B1) 37(8B2) 39(8B1) 40(7B2) 41(7B1) 42(6B2) 43(6B1) 44(5B2); RU49 1(NC)* 6(A5) 7(A6) 9(A8) 11(B8) 13(B6) 14(B5); RU89 10(3B2) 13(4B2); RU94 45(5B1); RU99 29(12B2) 30(12B1) 31(11B2) 33(10B2); RU103 1(NC)*; RU113 10(3B2) 11(3B1) 13(4B2) 14(4B1); RU116 10(3B2) 11(3B1) 13(4B2) 14(4B1); RU118 10(3B2) 11(3B1) 13(4B2) 14(4B1); U22 1(NC1); U106 1(NC1); U1018 3(ALERT/NC.3); U1019 3(ALERT/NC.3); U1020 3(ALERT/NC.3); U1021 3(ALERT/NC.3); U1022 3(ALERT/NC.3); U1023 3(ALERT/NC.3); U1024 3(ALERT/NC.3); U1025 3(ALERT/NC.3); U1026 3(ALERT/NC.3); U1031 3(ALERT/NC.3); U1035 1(NC1); U1036 1(NC1)

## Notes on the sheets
sheet 58
- 100-0111 (0x47)
- 100-0000 (0x40)
- 100-0100 (0x44)
- 100-1000 (0x48)
- 100-0001 (0x41)
- 100-0101 (0x45)
- 100-0010 (0x42)
- 100-0110 (0x46)
- 100-0011 (0x43)
- 100-1001 (0x49)
- ER5
sheet 59
- ER21
- DARA Bd Interface Connector
- DARA Bd can be interfaced to conduct more in-depth
  power measurements.
  All Vdiff signal pairs (P & N) shown should be routed as
  pseudo-Diff Pair segments using min trace widths since
  these are low voltage sensing nets, not power delivery nets.
- Vdiff, P
- Vdiff, P
- R1010
- Vdiff, N
- Vdiff, N
- HIGH > 2.5V TO TURN POWER ON
- Vdiff, P
- Vdiff, P
- R1016
- PB_ON IS 12 VOLT SIGNAL
- Vdiff, N
- Vdiff, N
- Vdiff, P
- Vdiff, P
- R1023
- Vdiff, N
- Vdiff, N
- Vdiff, P
- Vdiff, P
- R1020
- Vdiff, N
- Vdiff, N
- BOOT SWITCHES SHOULD BE SET
  TO OFF FOR PULLDOWNS.
  AUTOMATION WILL DRIVE HIGH
  TO OVERRIDE.
- Vdiff, P
- R1018
- Vdiff, P
- Vdiff, N
- Vdiff, N
- R1011
- Vdiff, P
- SYSBOOT0
- Vdiff, P
- SYSBOOT1
- SYSBOOT2
- ER22
- Vdiff, N
- Vdiff, N
- SYSBOOT3
- SYSBOOT4
- AUTOMATION INTERFACE
- SYSBOOT5
- Vdiff, P
- R1014
- Vdiff, P
- ALL SIGNALS SHOULD BE
  REFERENCED TO EVM_3V3
- Vdiff, N
- Vdiff, N
- R1013
- Cable : Parlex-050R40-76B, .5mm 3"
- Vdiff, P
- Vdiff, P
- Vdiff, N
- Vdiff, N
- Vdiff, P
- GPIO
- Vdiff, N
- GPIO
- Vdiff, P
- GND
- Vdiff, N
- GND
- PM_I2C HAVE ON BOARD PULLUPS.
  AUTOMATION SHOULD BE WEAK
  ~20K OR HIGHER.
sheet 61
- MMC3_D7/VIN2B_CLK1/AB5/P1.P17
sheet 62
- GPIO6_10/VIN2B_HSYNC/AC5/P3.P31
- GPIO6_11/VIN2B_VSYNC/AB4/P3.P33
- 50 OHMS FOR R776 AND R777 WHEN POPULATED
  BASED ON SIMULATION
- PULLUPS AT HDMI
sheet 63
- DEFAULTS TO GPMC FOR BOOTING
- A = B1 LLH : GPMC, xxx_S2=1,xxx_S0=1
  A = B2 LHL : VOUT, xxx_S2=1,xxx_S0=0
  A = B3 HLH : VIN , xxx_S2=0,xxx_S0=1
- gpmc_ad[0]
  gpmc_ad[1]
  gpmc_ad[2]
  gpmc_ad[3]
  gpmc_ad[4]
  gpmc_ad[5]
  gpmc_ad[6]
  gpmc_ad[7]
  gpmc_ad[8]
  gpmc_ad[9]
  gpmc_ad[10]
  gpmc_ad[11]
  gpmc_ad[12]
  gpmc_ad[13]
  gpmc_ad[14]
  gpmc_ad[15]
  gpmc_a[0]
  gpmc_a[1]
  gpmc_a[2]
  gpmc_a[3]
  gpmc_a[4]
  gpmc_a[5]
  gpmc_a[6]
  gpmc_a[7]
  gpmc_a[8]
  gpmc_a[9]
  gpmc_a[10]
  gpmc_a[11]
- vout3_d[0]
  vout3_d[1]
  vout3_d[2]
  vout3_d[3]
  vout3_d[4]
  vout3_d[5]
  vout3_d[6]
  vout3_d[7]
  vout3_d[8]
  vout3_d[9]
  vout3_d[10]
  vout3_d[11]
  vout3_d[12]
  vout3_d[13]
  vout3_d[14]
  vout3_d[15]
  vout3_d[16]
  vout3_d[17]
  vout3_d[18]
  vout3_d[19]
  vout3_d[20]
  vout3_d[21]
  vout3_d[22]
  vout3_d[23]
  vout3_hsync
  vout3_vsync
  vout3_de
  vout3_fld
sheet 64
- 3.3 VOLT
- 1.8 VOLT
- DIFFERENTIAL PAIR
  90 OHM DIFFERENTIAL
  IMPEDANCE
  SHORT AND STRAIGHT AS
  POSSIBLE,
  MINIMUM NUMBER OF VIAS
sheet 65
- LLH  A1 TO B1
  LHL  A1 TO B2
- DEFAULT B2 - MDIO
- DEFAULT B2 - MDIO
sheet 66
- LLH  A1 TO B1
  LHL  A1 TO B2
- I2C5
- I2C3
sheet 67
- MUX L
- MUX K
- DCAN2 signaling is not SW controllable.
  Requires HW change: R264 = 10k & R265 =
  NO-POP
sheet 68
- DEFAULTS TO GPMC FOR BOOTING
- A = B1 LLH : GPMC, xxx_S2=1,xxx_S0=1
  A = B2 LHL : VOUT, xxx_S2=1,xxx_S0=0
  A = B3 HLH : VIN , xxx_S2=0,xxx_S0=1
- gpmc_ad[0]
  gpmc_ad[1]
  gpmc_ad[2]
  gpmc_ad[3]
  gpmc_ad[4]
  gpmc_ad[5]
  gpmc_ad[6]
  gpmc_ad[7]
  gpmc_ad[8]
  gpmc_ad[9]
  gpmc_ad[10]
  gpmc_ad[11]
  gpmc_ad[12]
  gpmc_ad[13]
  gpmc_ad[14]
  gpmc_ad[15]
  gpmc_a[0]
  gpmc_a[1]
  gpmc_a[2]
  gpmc_a[3]
  gpmc_a[4]
  gpmc_a[5]
  gpmc_a[6]
  gpmc_a[7]
  gpmc_a[8]
  gpmc_a[9]
  gpmc_a[10]
  gpmc_a[11]
- vout3_d[0]
  vout3_d[1]
  vout3_d[2]
  vout3_d[3]
  vout3_d[4]
  vout3_d[5]
  vout3_d[6]
  vout3_d[7]
  vout3_d[8]
  vout3_d[9]
  vout3_d[10]
  vout3_d[11]
  vout3_d[12]
  vout3_d[13]
  vout3_d[14]
  vout3_d[15]
  vout3_d[16]
  vout3_d[17]
  vout3_d[18]
  vout3_d[19]
  vout3_d[20]
  vout3_d[21]
  vout3_d[22]
  vout3_d[23]
  vout3_hsync
  vout3_vsync
  vout3_de
  vout3_fld
- gpmc_cs[3]
- vout3_clk
sheet 69
- REV C1, MOVE FROM 0x51 BACK TO 0x50
- PLACE TEMP SENSOR CLOSE TO PROCESSOR
- Preliminary Information - Subject to change
